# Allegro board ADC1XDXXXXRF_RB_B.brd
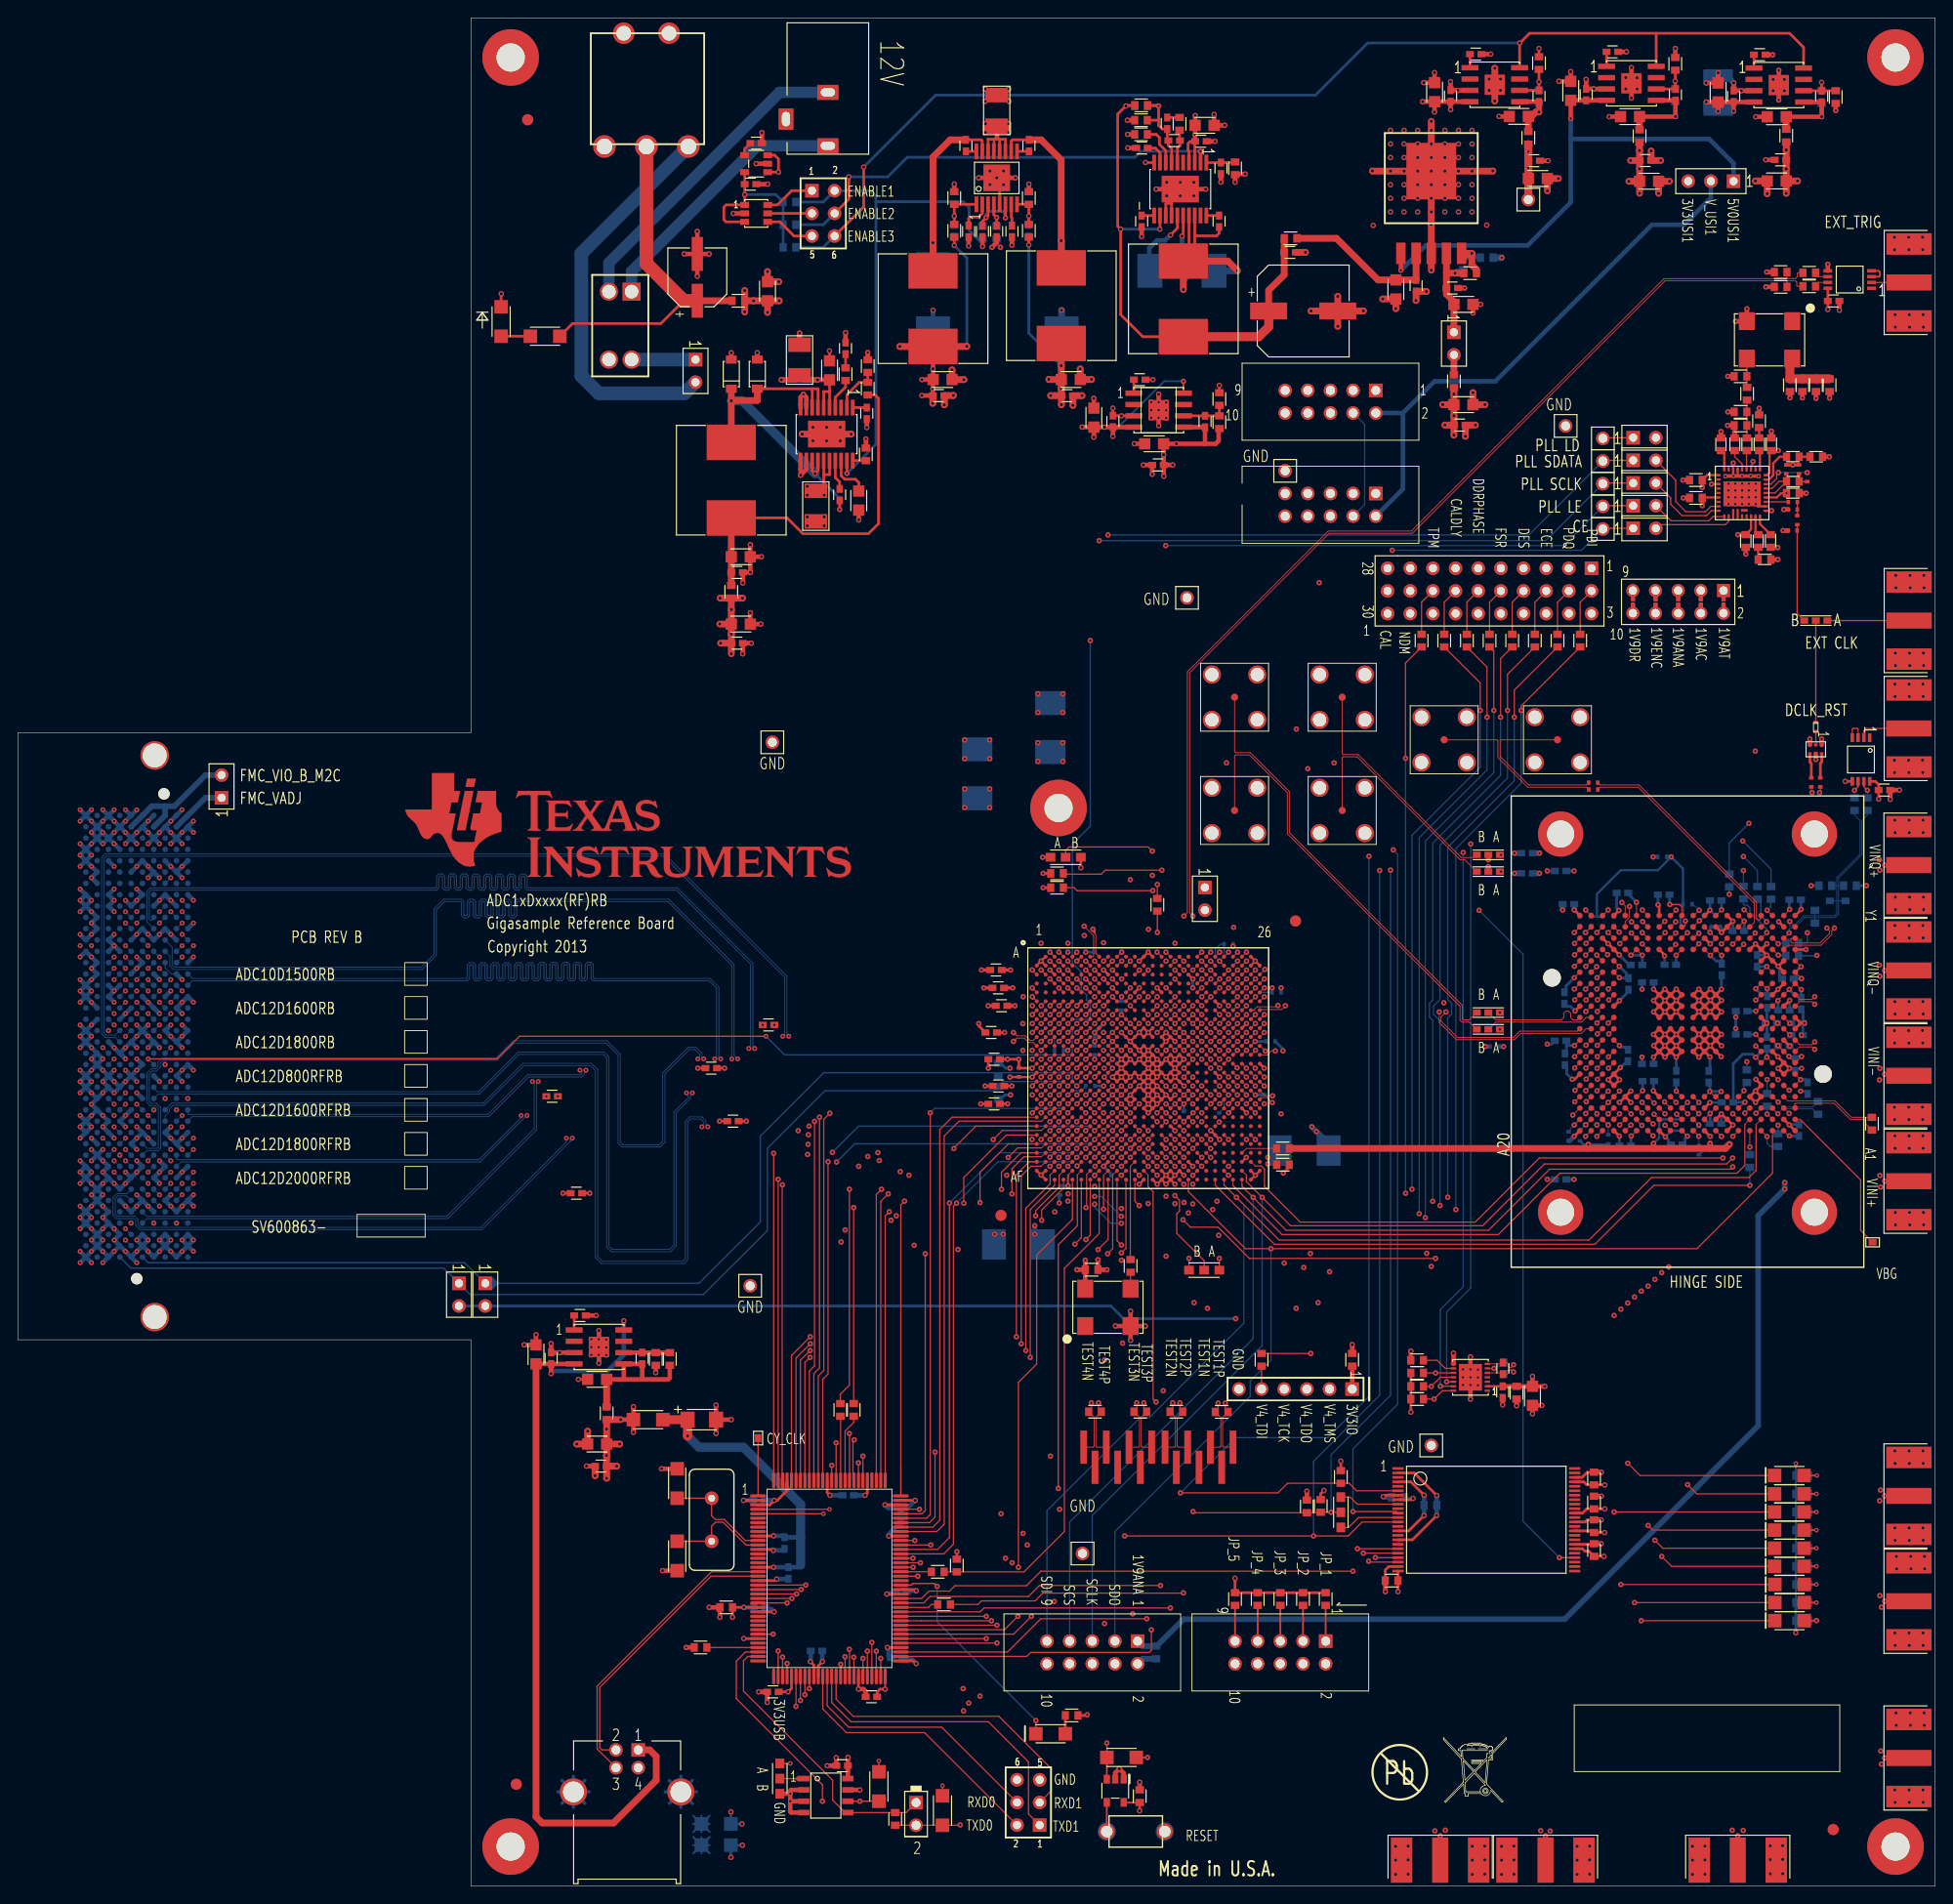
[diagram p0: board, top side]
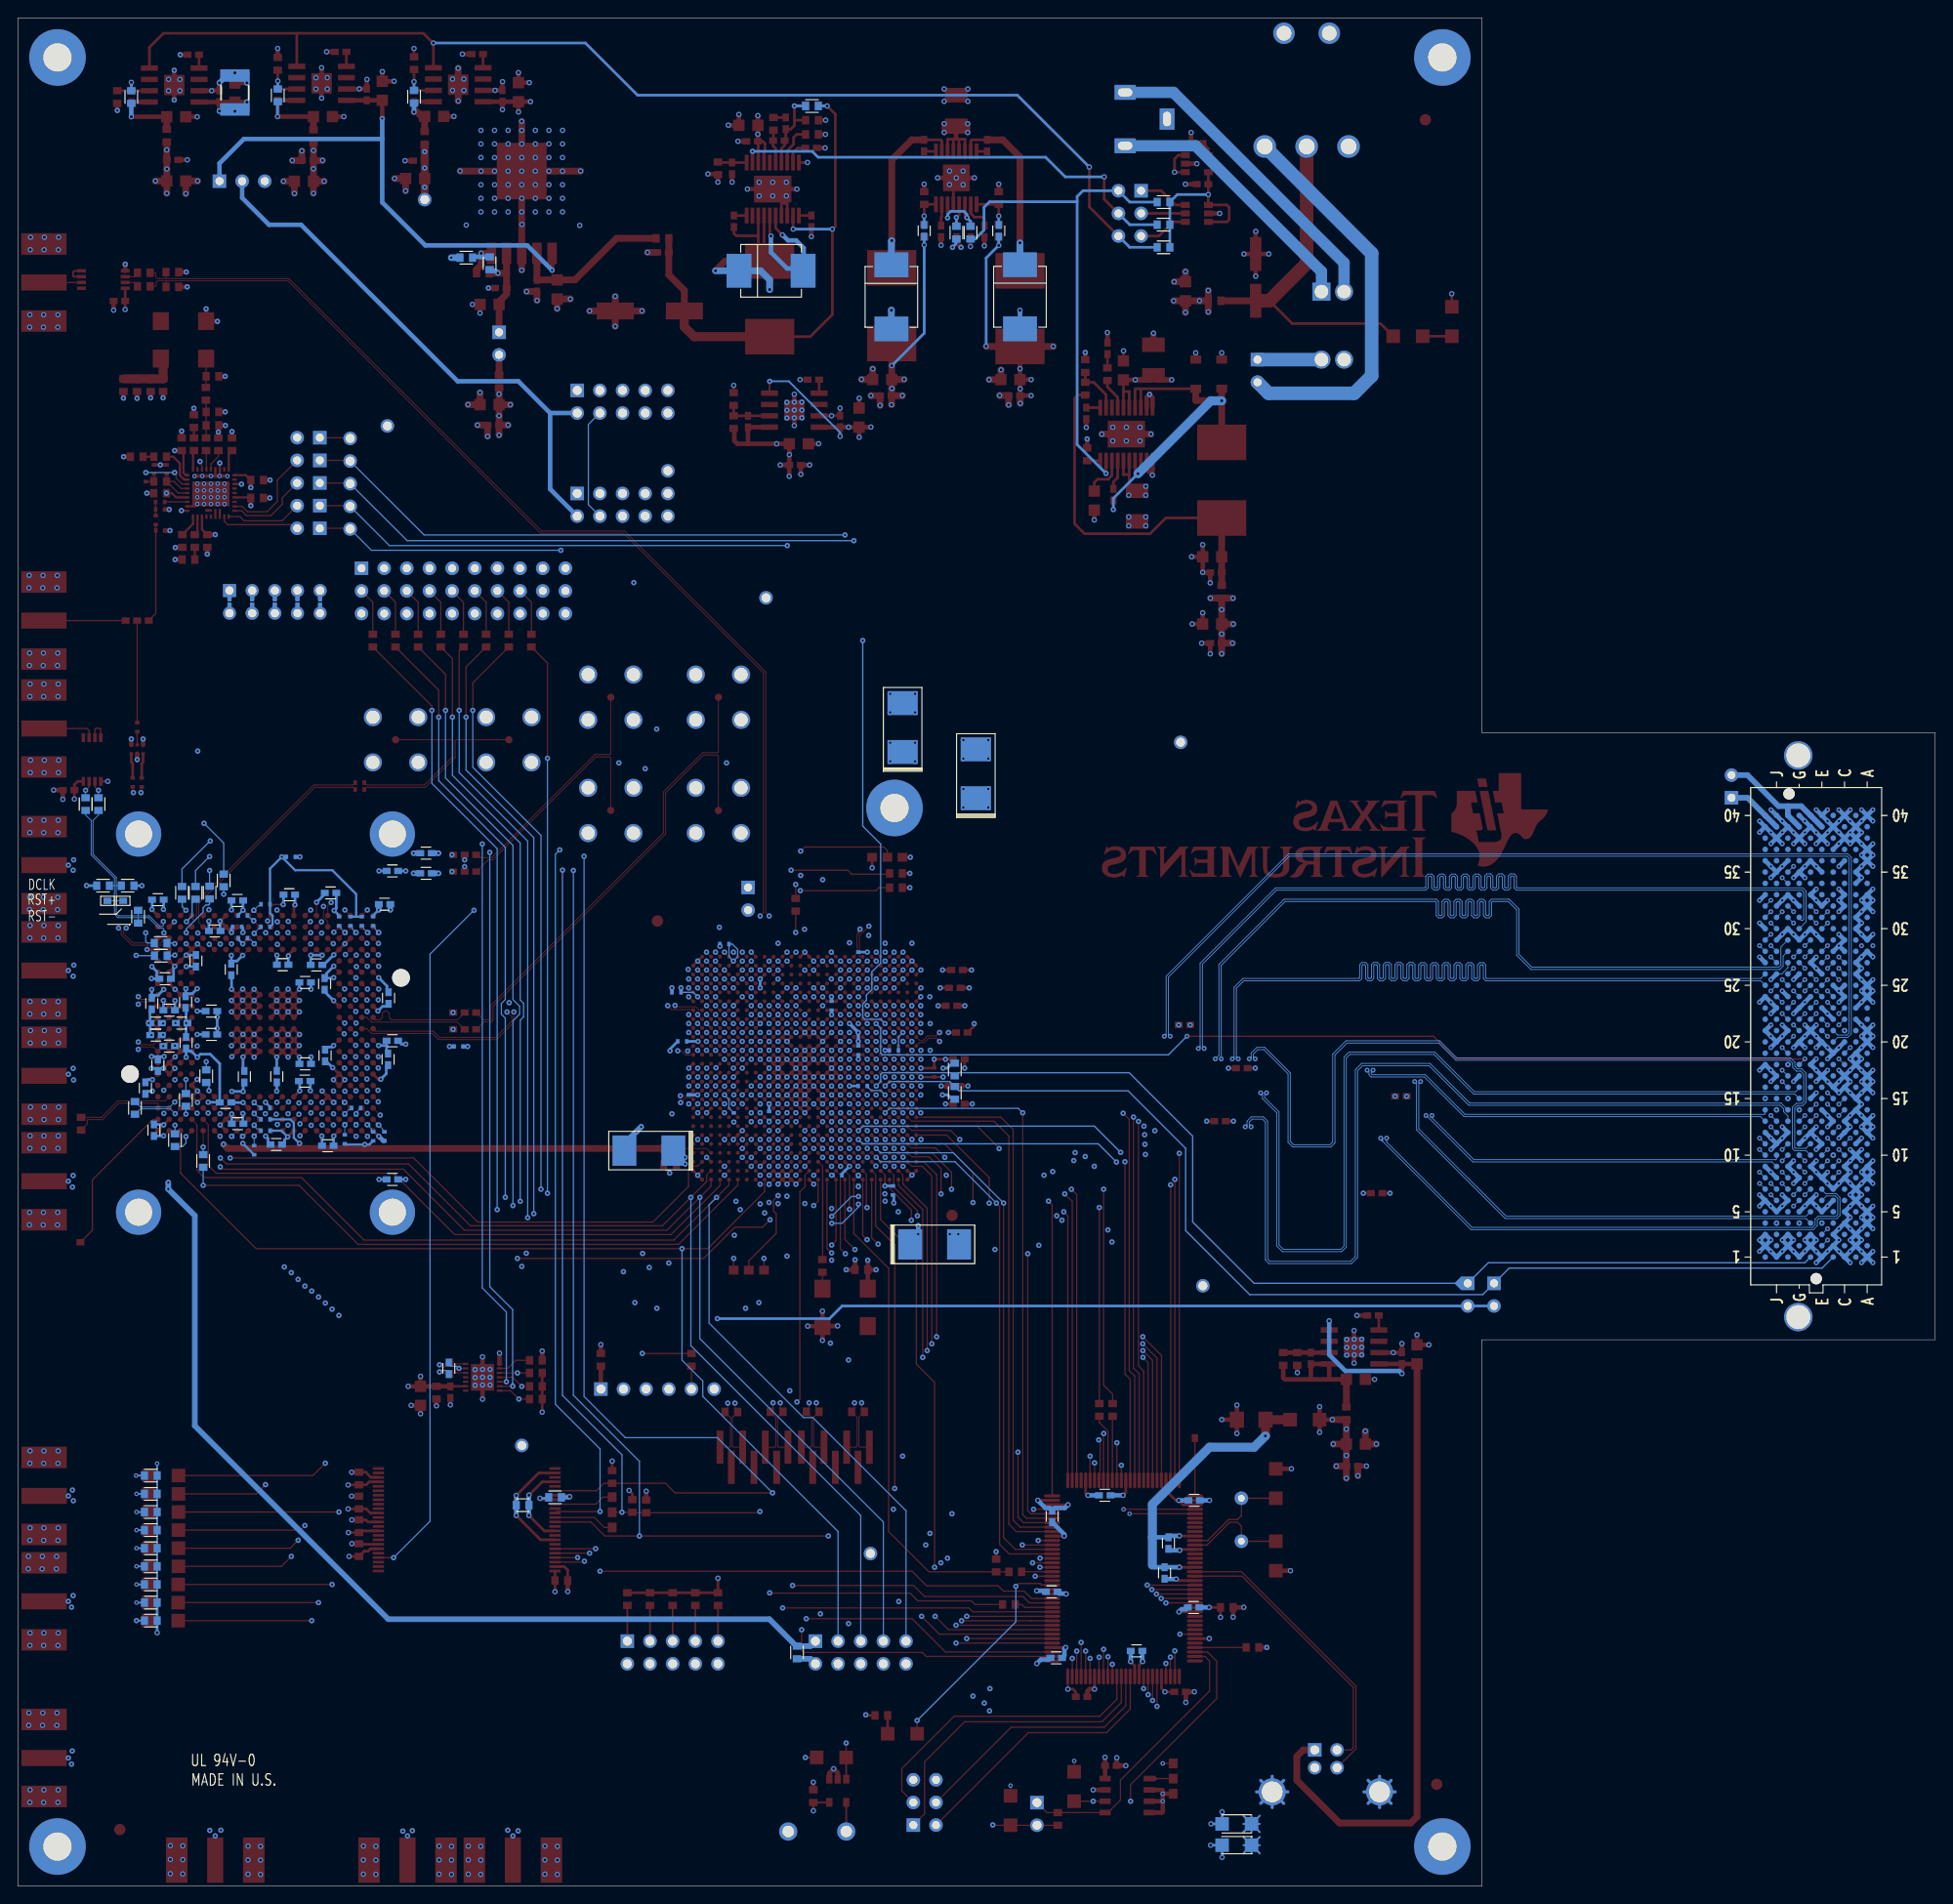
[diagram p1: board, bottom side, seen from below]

Outline 214.93 x 209.55 mm; copper layers: TOP, GND1, SIG1, PWR1, GND2, SIG2, PWR2, SIG3, GND3, BOTTOM. Coordinates in mm from the lower left corner of the outline.
Outline path: 0,129.36 50.8,129.36 50.8,209.55 214.93,209.55 214.93,0 50.8,0 50.8,61.29 0,61.29 0,129.36

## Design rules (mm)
net group CLK: nets CLK+ CLK-
net group DCLK_RST: nets DCLK_RST+ DCLK_RST-
net group DCLKI: nets DCLKI+ DCLKI-
net group DCLKQ: nets DCLKQ+ DCLKQ-
net group DCLKQ_OUT: nets DCLKQ+_OUT DCLKQ-_OUT
net group DCLKQ_PN: nets DCLKQ_N DCLKQ_P
net group DI0: nets DI+0 DI-0
net group DI1: nets DI+1 DI-1
net group DI2: nets DI+2 DI-2
net group DI3: nets DI+3 DI-3
net group DI4: nets DI+4 DI-4
net group DI5: nets DI+5 DI-5
net group DI6: nets DI+6 DI-6
net group DI7: nets DI+7 DI-7
net group DI8: nets DI+8 DI-8
net group DI9: nets DI+9 DI-9
net group DI10: nets DI+10 DI-10
net group DI11: nets DI+11 DI-11
net group DID0: nets DID+0 DID-0
net group DID1: nets DID+1 DID-1
net group DID2: nets DID+2 DID-2
net group DID3: nets DID+3 DID-3
net group DID4: nets DID+4 DID-4
net group DID5: nets DID+5 DID-5
net group DID6: nets DID+6 DID-6
net group DID7: nets DID+7 DID-7
net group DID8: nets DID+8 DID-8
net group DID9: nets DID+9 DID-9
net group DID10: nets DID+10 DID-10
net group DID11: nets DID+11 DID-11
net group DQ0: nets DQ+0 DQ-0
net group DQ1: nets DQ+1 DQ-1
net group DQ2: nets DQ+2 DQ-2
net group DQ3: nets DQ+3 DQ-3
net group DQ4: nets DQ+4 DQ-4
net group DQ5: nets DQ+5 DQ-5
net group DQ6: nets DQ+6 DQ-6
net group DQ7: nets DQ+7 DQ-7
net group DQ8: nets DQ+8 DQ-8
net group DQ9: nets DQ+9 DQ-9
net group DQ10: nets DQ+10 DQ-10
net group DQ11: nets DQ+11 DQ-11
net group DQD0: nets DQD+0 DQD-0
net group DQD1: nets DQD+1 DQD-1
net group DQD2: nets DQD+2 DQD-2
net group DQD3: nets DQD+3 DQD-3
net group DQD4: nets DQD+4 DQD-4
net group DQD5: nets DQD+5 DQD-5
net group DQD6: nets DQD+6 DQD-6
net group DQD7: nets DQD+7 DQD-7
net group DQD8: nets DQD+8 DQD-8
net group DQD9: nets DQD+9 DQD-9
net group DQD10: nets DQD+10 DQD-10
net group DQD11: nets DQD+11 DQD-11
net group EXT_TRIG: nets EXT_TRIG+ EXT_TRIG-
net group FMC_DCLK_DI: nets FMC_DCLK_DI+ FMC_DCLK_DI-
net group FMC_DCLK_DID: nets FMC_DCLK_DID+ FMC_DCLK_DID-
net group FMC_DCLK_DQ: nets FMC_DCLK_DQ+ FMC_DCLK_DQ-
net group FMC_DCLK_DQD: nets FMC_DCLK_DQD+ FMC_DCLK_DQD-
net group FMC_DI0: nets FMC_DI+0 FMC_DI-0
net group FMC_DI1: nets FMC_DI+1 FMC_DI-1
net group FMC_DI2: nets FMC_DI+2 FMC_DI-2
net group FMC_DI3: nets FMC_DI+3 FMC_DI-3
net group FMC_DI4: nets FMC_DI+4 FMC_DI-4
net group FMC_DI5: nets FMC_DI+5 FMC_DI-5
net group FMC_DI6: nets FMC_DI+6 FMC_DI-6
net group FMC_DI7: nets FMC_DI+7 FMC_DI-7
net group FMC_DI8: nets FMC_DI+8 FMC_DI-8
net group FMC_DI9: nets FMC_DI+9 FMC_DI-9
net group FMC_DI10: nets FMC_DI+10 FMC_DI-10
net group FMC_DI11: nets FMC_DI+11 FMC_DI-11
net group FMC_DID0: nets FMC_DID+0 FMC_DID-0
net group FMC_DID1: nets FMC_DID+1 FMC_DID-1
net group FMC_DID2: nets FMC_DID+2 FMC_DID-2
net group FMC_DID3: nets FMC_DID+3 FMC_DID-3
net group FMC_DID4: nets FMC_DID+4 FMC_DID-4
net group FMC_DID5: nets FMC_DID+5 FMC_DID-5
net group FMC_DID6: nets FMC_DID+6 FMC_DID-6
net group FMC_DID7: nets FMC_DID+7 FMC_DID-7
net group FMC_DID8: nets FMC_DID+8 FMC_DID-8
net group FMC_DID9: nets FMC_DID+9 FMC_DID-9
net group FMC_DID10: nets FMC_DID+10 FMC_DID-10
net group FMC_DID11: nets FMC_DID+11 FMC_DID-11
net group FMC_DQ0: nets FMC_DQ+0 FMC_DQ-0
net group FMC_DQ1: nets FMC_DQ+1 FMC_DQ-1
net group FMC_DQ2: nets FMC_DQ+2 FMC_DQ-2
net group FMC_DQ3: nets FMC_DQ+3 FMC_DQ-3
net group FMC_DQ4: nets FMC_DQ+4 FMC_DQ-4
net group FMC_DQ5: nets FMC_DQ+5 FMC_DQ-5
net group FMC_DQ6: nets FMC_DQ+6 FMC_DQ-6
net group FMC_DQ7: nets FMC_DQ+7 FMC_DQ-7
net group FMC_DQ8: nets FMC_DQ+8 FMC_DQ-8
net group FMC_DQ9: nets FMC_DQ+9 FMC_DQ-9
net group FMC_DQ10: nets FMC_DQ+10 FMC_DQ-10
net group FMC_DQ11: nets FMC_DQ+11 FMC_DQ-11
net group FMC_DQD0: nets FMC_DQD+0 FMC_DQD-0
net group FMC_DQD1: nets FMC_DQD+1 FMC_DQD-1
net group FMC_DQD2: nets FMC_DQD+2 FMC_DQD-2
net group FMC_DQD3: nets FMC_DQD+3 FMC_DQD-3
net group FMC_DQD4: nets FMC_DQD+4 FMC_DQD-4
net group FMC_DQD5: nets FMC_DQD+5 FMC_DQD-5
net group FMC_DQD6: nets FMC_DQD+6 FMC_DQD-6
net group FMC_DQD7: nets FMC_DQD+7 FMC_DQD-7
net group FMC_DQD8: nets FMC_DQD+8 FMC_DQD-8
net group FMC_DQD9: nets FMC_DQD+9 FMC_DQD-9
net group FMC_DQD10: nets FMC_DQD+10 FMC_DQD-10
net group FMC_DQD11: nets FMC_DQD+11 FMC_DQD-11
net group FMC_ORI: nets FMC_ORI+ FMC_ORI-
net group FMC_ORQ: nets FMC_ORQ+ FMC_ORQ-
net group FMC_RCOUT1: nets FMC_RCOUT1+ FMC_RCOUT1-
net group FMC_RCOUT2: nets FMC_RCOUT2+ FMC_RCOUT2-
net group ORI: nets ORI+ ORI-
net group ORQ: nets ORQ+ ORQ-
net group RCLK: nets RCLK+ RCLK-
net group RCLK_IN: nets RCLK+_IN RCLK-_IN
net group RCOUT1: nets RCOUT1+ RCOUT1-
net group RCOUT1_OUT: nets RCOUT1+_OUT RCOUT1-_OUT
net group RCOUT1_PN: nets RCOUT1N RCOUT1P
net group RCOUT2: nets RCOUT2+ RCOUT2-
net group REXT: nets N17676520 N17676524
net group RTRIM: nets N17676530 N17676534
net group TEST1: nets TEST1N TEST1P
net group TEST2: nets TEST2N TEST2P
net group TEST3: nets TEST3N TEST3P
net group TEST4: nets TEST4N TEST4P
net group TEST_TRACE: nets N16663537 N16663541
net group VINI: nets VINI+ VINI-
net group VINQ: nets VINQ+ VINQ-
net group TDIODE: nets ADC_TDIODE+ ADC_TDIODE- N16802193

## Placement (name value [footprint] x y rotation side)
ADC_CALIBRATION  GREEN  [R1206]  198.58 37.9 180 top
ADC_POWER  GREEN  [R1206]  198.58 39.93 180 top
C1  100n  [C0402]  199.68 84.79 90 bottom
C1_LF  See Chart  [R0402_NO_SS]  198.25 158.9 90 top
C2  100n  [C0402]  199.24 110.64 0 bottom
C2_LF  See Chart  [C0603]  198.98 157.56 0 top
C3  100n  [C0402]  198.42 101.78 180 bottom
C4  100n  [C0402]  191.01 102.82 270 bottom
C5  100n  [C0402]  189.54 90.79 90 bottom
C6  100n  [C0402]  192.86 107.14 180 bottom
C7  100n  [C0402]  200.63 89.51 270 bottom
C18  100n  [C0402]  184.51 111.2 180 bottom
C19  100n  [C0402]  185.25 103.35 180 bottom
C20  100n  [C0402]  173.38 99.61 270 bottom
C21  100n  [C0402]  179.88 111.4 180 bottom
C22  100n  [C0402]  181.46 103.33 180 bottom
C23  100n  [C0402]  180.55 101.2 270 bottom
C24  100n  [C0402]  180.49 93.17 270 bottom
C25  100n  [C0402_NO_SS]  178.92 87.91 0 bottom
C26  100n  [C0402]  182.78 90.3 0 bottom
C27  100n  [C0402]  180.19 83.05 180 bottom
C28  100n  [C0402]  185.96 83.18 180 bottom
C29  100n  [C0402]  185.91 90.8 90 bottom
C30  100n  [C0402]  173.43 92.74 270 bottom
C34  100n  [C0402]  199.24 92.08 270 bottom
C35  100n  [C0402]  196.08 94.59 90 bottom
C36  100n  [C0402]  199.92 98.99 270 bottom
C37  100n  [C0402]  196.57 96.8 180 bottom
C38  100n  [C0402]  196.13 99.16 270 bottom
C39  100n  [C0402]  197.97 94.22 0 bottom
C40  100n  [C0402]  197.97 98.25 0 bottom
C41  100n  [C0402]  191.65 87.91 180 bottom
C46  100n  [C0402_NO_SS]  190.35 84.1 180 bottom
C47  100n  [C0402]  190.3 85.52 0 bottom
C48  100n  [C0402]  190.33 110.56 180 bottom
C49  100n  [C0402_NO_SS]  190.35 107.59 0 bottom
C52  100n  [C0402]  194.97 103.78 90 bottom
C54  100n  [C0402]  83.07 43.27 0 bottom
C55  100n  [C0402]  83.13 31.27 0 bottom
C56  100n  [C0402]  89.53 26.39 0 bottom
C57  100n  [C0402]  84.65 21.8 180 top
C58  100n  [C0402]  95.69 21.24 180 top
C59  100n  [C0402]  98.53 25.6 0 bottom
C60  100n  [C0402]  99.03 33.02 180 bottom
C61  100n  [C0402]  98.98 41.48 270 bottom
C62  100n  [C0402]  93.09 43.84 180 bottom
C63  0.001uF  [C0603]  79.41 31.27 180 top
C64  2.2uF  [C3216]  76.67 52.32 0 top
C65  10n  [C0402]  86.39 35.13 270 bottom
C66  100n  [C0402]  85.95 38.48 270 bottom
C67  100n  [C0603]  125.76 10.09 90 top
C68  100n  [C0402]  92.41 13.51 180 top
C69  4.7n  [C1206]  78.29 4.6 180 bottom
C70  12pF  [C1206]  73.91 45.16 90 top
C71  12pF  [C1206]  73.91 37.03 270 top
C72  100n  [C0402]  193.23 95.53 180 bottom
C73  100n  [C0402]  199.45 96.8 0 bottom
C74  100n  [C0603]  149.58 59.04 90 top
C75  100p  [C0402]  166.62 58.08 90 bottom
C76  100p  [C0402]  166.48 58.08 90 top
C77  100p  [C0402]  166.45 55.41 270 top
C78  100n  [C0603]  120.37 69.14 0 top
C79  100n  [C0402]  193.23 98.15 180 bottom
C80  10n  [C0402_NO_SS]  126.21 87.74 0 bottom
C81  100n  [C0402_NO_SS]  127.21 95.75 180 bottom
C82  10n  [C0402_NO_SS]  125.21 100.75 0 bottom
C83  100n  [C0402_NO_SS]  128.21 100.75 180 bottom
C84  10n  [C0402_NO_SS]  124.21 82.74 0 bottom
C85  100n  [C0402_NO_SS]  129.2 82.74 180 bottom
C86  10n  [C0402_NO_SS]  125.23 103.76 0 bottom
C87  100n  [C0402_NO_SS]  129.21 103.76 180 bottom
C88  10n  [C0402_NO_SS]  123.06 79.74 180 bottom
C89  10n  [C0402_NO_SS]  131.22 97.75 180 bottom
C90  10n  [C0402_NO_SS]  131.72 102.25 270 bottom
C91  10n  [C0402_NO_SS]  132.22 100.75 180 bottom
C92  10n  [C0402_NO_SS]  132.71 96.25 270 bottom
C93  100n  [C0402_NO_SS]  135.72 105.66 0 bottom
C94  10n  [C0402_NO_SS]  117.71 104.26 90 bottom
C95  10n  [C0402_NO_SS]  118.22 98.75 0 bottom
C96  10n  [C0402_NO_SS]  120.71 104.26 90 bottom
C97  100n  [C0402_NO_SS]  121.21 95.75 0 bottom
C98  100n  [C0402_NO_SS]  128.71 80.24 270 bottom
C99  10n  [C0402_NO_SS]  131.72 96.25 270 bottom
C100  10n  [C0402_NO_SS]  114.22 98.75 180 bottom
C101  10n  [C0402_NO_SS]  120.71 100.25 270 bottom
C102  10n  [C0402_NO_SS]  129.72 85.24 270 bottom
C103  10n  [C0402_NO_SS]  132.22 85.74 0 bottom
C104  10n  [C0402_NO_SS]  132.22 86.74 0 bottom
C105  10n  [C0402_NO_SS]  131.72 83.24 90 bottom
C106  100n  [C0402_NO_SS]  131.72 80.24 90 bottom
C107  100n  [C0402_NO_SS]  135.22 83.74 180 bottom
C108  10n  [C0402_NO_SS]  114.2 83.75 180 bottom
C109  10n  [C0402_NO_SS]  118.21 83.75 0 bottom
C110  10n  [C0402_NO_SS]  116.84 78.03 270 bottom
C111  10n  [C0402_NO_SS]  121.71 88.24 90 bottom
C114  10n  [C0402_NO_SS]  131.72 94.25 90 bottom
C115  10n  [C0402_NO_SS]  132.72 94.25 270 bottom
C116  10n  [C0402_NO_SS]  132.72 89.25 90 bottom
C117  10n  [C0402_NO_SS]  135.72 95.25 90 bottom
C118  10n  [C0402_NO_SS]  134.67 86.22 270 bottom
C119  100n  [C0402_NO_SS]  140.45 94.75 0 bottom
C120  10n  [C0402_NO_SS]  112.21 91.28 270 top
C121  10n  [C0402_NO_SS]  114.2 93.75 180 bottom
C122  10n  [C0402_NO_SS]  114.22 88.75 180 bottom
C123  10n  [C0402_NO_SS]  116.73 93.75 180 bottom
C124  10n  [C0402_NO_SS]  120.22 89.75 0 bottom
C125  100n  [C0402_NO_SS]  120.71 93.75 270 bottom
C126  100n  [C0402_NO_SS]  130.22 78.75 180 bottom
C128  10n  [C0402_NO_SS]  122.21 94.75 180 bottom
C129  10n  [C0402_NO_SS]  122.21 93.75 180 bottom
C130  10n  [C0402_NO_SS]  122.22 89.75 180 bottom
C131  10n  [C0402_NO_SS]  122.71 88.24 270 bottom
C132  10n  [C0402_NO_SS]  123.21 95.75 0 bottom
C134  10n  [C0402_NO_SS]  124.21 88.75 0 bottom
C135  10n  [C0402_NO_SS]  124.21 87.74 0 bottom
C136  100n  [C0603]  168.01 55.35 270 top
C137  100n  [C0603]  200.05 168.35 90 top
C138  100pF  [C0603]  198.65 168.35 90 top
C139  100n  [C0603]  193.83 161.72 270 top
C140  100n  [C0603]  192.46 161.72 270 top
C142  0.47uF  [C0603]  195.2 161.72 90 top
C143  10n  [C0603]  190.93 161.72 90 top
C144  100pF  [C0603]  188.11 157.71 180 top
C145  100pF  [C0603]  196.57 161.72 270 top
C147  0.47uF  [C0603]  198.98 160.32 180 top
C149  100n  [C0603]  188.11 155.7 0 top
C153  100pF  [C0603]  198.98 156.24 0 top
C154  4.7uF  [C0603]  195.1 150.88 270 top
C155  100n  [C0603]  196.49 150.88 90 top
C156  100n  [C0603]  193.7 150.88 90 top
C157  100uF  [C6P6MMX6P6MM]  76.17 180.44 90 top
C158  4.7uF  [C1210]  87.63 171.17 90 top
C159  4.7uF  [C1210]  109.74 199.16 90 top
C160  10u  [C0805]  84.04 178.88 90 top
C161  0.22uF  [C0402]  109.72 185.6 270 top
C162  100n  [C0603]  176.7 40.37 90 top
C163  100n  [C0603]  158.35 42.74 0 bottom
C164  0.1u  [C0402]  106.28 195.22 270 top
C165  0.1u  [C0402]  113.34 195.22 270 top
C166  100n  [C0603]  154.71 43.61 180 bottom
C167  0.1u  [C0402]  103.23 167.19 0 top
C168  10u  [C0805]  103.67 168.98 0 top
C169  10u  [C0805]  118.04 168.98 0 top
C170  0.1u  [C0402]  117.63 167.17 0 top
C171  100n  [C0603]  154.01 34.27 180 top
C172  100n  [C0603]  176.7 37.7 90 top
C173  100n  [C0603]  176.7 45.72 90 top
C174  100n  [C0603]  176.7 43.03 90 top
C175  0.1u  [C0402]  106.58 185.6 270 top
C176  0.1u  [C0402]  111.44 185.6 270 top
C177  1u  [C0402]  108.14 185.6 270 top
C178  27nF  [C0402]  104.97 185.67 270 bottom
C179  27nF  [C0402]  113.33 185.67 270 bottom
C180  10u  [C0805]  120.62 164.71 90 top
C181  0.1u  [C0402]  122.76 164.29 90 top
C182  10u  [C0805]  127.38 161.78 180 top
C183  0.1u  [C0402]  127.81 159.4 180 top
C184  0.1u  [C0402]  80.63 139.42 0 top
C185  0.1u  [C0402]  133.09 164.26 270 top
C186  0.01u  [C0402]  125.76 168.96 0 top
C187  10uF  [1812]  190.61 201.17 90 bottom
C188  0.1u  [C0402]  134.87 192.67 90 top
C189  See Chart  [C0402]  134.66 186.73 270 top
C190  1uF  [C0603]  136.45 192.67 270 top
C191  1u  [C0402]  129.62 195.78 0 top
C192  10u  [C0805]  133.04 197.5 0 top
C193  0.1u  [C0402]  132.62 195.7 0 top
C194  270u  [C10P3MMX10P3MM]  144.09 176.67 0 top
C195  0.1u  [C0402]  142.61 183.24 0 top
C196  0.1u  [C0402]  156.75 179.51 270 top
C197  0.1u  [C0402]  80.62 147.35 0 top
C198  10u  [C0805]  154.48 179.09 270 top
C201  100n  [C0402]  160.8 179.25 0 top
C202  10n  [C0402]  128.85 197.73 90 top
C205  0.01u  [C0402]  125.98 186.73 270 top
C206  100p  [C0402]  126.01 194.96 180 top
C207  10u  [C0805]  190.61 201.17 90 top
C208  0.1u  [C0402]  192.35 200.75 90 top
C209  10u  [C0805]  197.18 198.46 180 top
C210  0.1u  [C0402]  197.59 193.62 180 top
C211  10u  [C0805]  197.18 191.25 180 top
C212  0.1u  [C0402]  202.21 200.73 270 top
C213  10u  [C0805]  58.08 59.65 90 top
C214  0.1u  [C0402]  59.78 59.22 90 top
C215  10u  [C0805]  64.94 56.85 180 top
C216  0.1u  [C0402]  65.36 47.11 180 top
C217  10u  [C0805]  64.94 49.59 180 top
C218  0.01u  [C0402]  195.27 205.41 0 top
C219  0.1u  [C0402]  69.99 59.19 270 top
C220  0.01u  [C0402]  63.01 64.01 0 top
C221  10u  [C0805]  174.08 201.37 90 top
C222  0.1u  [C0402]  175.81 200.95 90 top
C223  10u  [C0805]  180.73 198.47 180 top
C224  0.1u  [C0402]  182.45 193.55 0 top
C225  10u  [C0805]  182.86 191.22 0 top
C226  0.1u  [C0402]  185.82 200.92 270 top
C227  0.01u  [C0402]  178.75 205.73 0 top
C228  10u  [C0805]  158.82 201.21 90 top
C229  0.1u  [C0402]  160.61 200.79 90 top
C230  10u  [C0805]  168.26 198.49 180 top
C231  0.1u  [C0402]  169.98 193.53 0 top
C232  10u  [C0805]  170.4 191.53 0 top
C233  0.1u  [C0402]  170.52 200.77 270 top
C234  0.01u  [C0402]  163.44 205.48 0 top
C235  100n  [C0402]  95.16 165.19 270 top
C236  2.2n  [C0402]  92.79 172.48 90 top
C237  1u  [C0805]  94.26 155.4 270 top
C238  100n  [C0402]  92.13 156.07 270 top
C239  10u  [C0805]  81.04 149.11 0 top
C240  1uF  [C0603]  201.57 168.35 270 top
C241  10u  [C0805]  169.79 54.99 270 top
C242  10u  [C0805]  162.05 166.16 0 top
C243  10u  [C0805]  81.05 141.56 0 top
C244  0.1u  [C0402]  161.64 163.87 0 top
C245  10n  [C0402]  209.25 122.94 0 top
C246  10n  [C0402]  203.55 177.79 0 top
C247  1800pF  [C0603]  162.8 180.91 0 top
C248  10u  [C0805]  162.05 177.41 0 top
C249  100n  [C0402]  109.11 95.75 0 top
C250  100n  [C0402]  109.44 92.75 0 top
C251  100n  [C0402]  109.93 89.75 0 top
C252  100n  [C0402]  109.44 87.74 0 top
C253  100n  [C0402_NO_SS]  130.72 86.39 90 bottom
C254  100n  [C0402]  172.95 113.87 180 bottom
C255  100n  [C0402]  172.95 94.82 180 bottom
C256  100n  [C0402]  172.95 79.27 180 bottom
C257  100n  [C0402]  173.82 110.13 0 bottom
C258  100n  [C0402]  182.73 101.36 0 bottom
C259  100n  [C0402]  182.72 92.23 0 bottom
C260  100n  [C0402_NO_SS]  177.01 86 90 bottom
C261  100n  [C0402]  84.15 96.6 0 top
C262  100n  [C0402]  77.72 91.75 0 top
C263  100n  [C0402]  80.16 85.8 0 top
C264  100n  [C0402]  59.89 88.6 0 top
C265  100n  [C0402]  62.61 77.72 0 top
C266  0.01u  [C0402]  82.77 195.49 0 top
C267  0.1u  [C0402]  82.13 190.89 0 top
C268  100n  [C0402]  199.45 95.45 0 bottom
C269  0.1uF  [C0805]  91 170.01 90 top
C270  4.7uF  [C1210]  89.46 154.79 270 top
C271  100n  [C0402_NO_SS]  122.21 96.75 0 bottom
C272  1u  [C0402_NO_SS]  123.71 98.76 90 bottom
C273  100n  [C0402_NO_SS]  135.21 98.75 180 bottom
C274  1u  [C0402_NO_SS]  141.1 100.25 0 bottom
C275  1u  [C0402_NO_SS]  138.22 83.74 180 bottom
C276  470u  [CAP_C-CASE]  144.2 82.5 0 bottom
C277  10n  [C0402_NO_SS]  122.21 92.75 180 bottom
C278  10n  [C0402_NO_SS]  124.21 86.74 0 bottom
C279  10n  [C0402_NO_SS]  124.21 96.75 180 bottom
C280  10n  [C0402_NO_SS]  123.2 85.74 180 bottom
C281  10n  [C0402_NO_SS]  125.71 96.25 270 bottom
C282  10n  [C0402_NO_SS]  127.21 86.74 180 bottom
C283  100n  [C0402_NO_SS]  129.21 97.75 180 bottom
C284  100n  [C0402_NO_SS]  129.21 86.74 0 bottom
C285  100n  [C0402_NO_SS]  132.22 92.75 0 bottom
C286  10n  [C0402_NO_SS]  123.21 91.75 0 bottom
C287  1u  [C0402_NO_SS]  130.22 91.75 180 bottom
C288  1u  [C0402_NO_SS]  131.21 90.75 0 bottom
C290  470u  [CAP_C-CASE]  115.75 129.95 90 bottom
C291  10n  [C0402_NO_SS]  121.21 85.74 180 bottom
C292  100n  [C0402_NO_SS]  120.71 79.09 270 bottom
C293  1u  [C0402_NO_SS]  122.21 86.74 180 bottom
C294  470u  [CAP_C-CASE]  112.17 71.98 180 bottom
C295  100n  [C0402_NO_SS]  139.72 88.24 270 bottom
C296  1u  [C0402_NO_SS]  139.72 91.25 90 bottom
C297  100n  [C0402_NO_SS]  121.78 91.25 90 bottom
C299  10n  [C0402_NO_SS]  124.71 95.25 270 bottom
C300  10n  [C0402_NO_SS]  123.71 93.25 270 bottom
C301  10n  [C0402_NO_SS]  123.71 90.25 90 bottom
C302  10n  [C0402_NO_SS]  124.71 93.25 270 bottom
C303  10n  [C0402_NO_SS]  124.71 90.25 90 bottom
C304  10n  [C0402_NO_SS]  127.71 93.25 270 bottom
C305  10n  [C0402_NO_SS]  128.71 89.23 270 bottom
C306  10n  [C0402_NO_SS]  128.71 96.24 270 bottom
C307  10n  [C0402_NO_SS]  128.71 94.26 90 bottom
C308  10n  [C0402_NO_SS]  129.72 90.25 90 bottom
C309  100n  [C0402_NO_SS]  128.21 87.74 180 bottom
C310  100n  [C0402_NO_SS]  129.72 95.25 270 bottom
C311  100n  [C0402_NO_SS]  130.72 96.25 90 bottom
C312  100n  [C0402_NO_SS]  129.72 93.25 270 bottom
C313  100n  [C0402_NO_SS]  130.73 89.25 90 bottom
C314  100n  [C0402_NO_SS]  129.72 88.25 90 bottom
C315  100n  [C0402_NO_SS]  131.22 87.74 0 bottom
C316  100n  [C0402_NO_SS]  130.72 93.25 270 bottom
C317  100n  [C0402_NO_SS]  131.72 89.25 90 bottom
C321  100p  [R0402_NO_SS]  198.98 155.24 0 top
C322  470u  [CAP_C-CASE]  107.54 124.76 90 bottom
C323  NA  [C0603]  127.58 26.21 270 bottom
C324  1u  [C0402_NO_SS]  135.72 80.24 90 bottom
C325  100n  [C0402]  110.27 98.75 0 top
C326  100n  [C0402]  109.91 100.75 0 top
C327  100n  [C0402]  109.65 102.76 0 top
C341  4.7n  [C0402_NO_SS]  202.06 123.8 270 top
C342  4.7n  [C0402_NO_SS]  201.05 123.8 270 top
C343  10pF  [C0402_NO_SS]  201.55 130 270 top
C362  100n  [C0402]  169.18 115.86 180 bottom
C363  100n  [C0402]  169.18 113.6 180 bottom
C364  100n  [C0402_NO_SS]  165.53 94.18 0 bottom
C365  100n  [C0402_NO_SS]  184.33 115.44 0 bottom
D1  DIODE SCHOTTKY  [SOD_123_21]  82.9 169.59 90 top
D2  DIODE SCHOTTKY  [DO214_AB]  102.59 178.26 90 bottom
D3  DIODE SCHOTTKY  [DO214_AB]  117.01 178.25 90 bottom
D4  DIODE SCHOTTKY  [DO214_AB]  130.5 181.18 0 bottom
D5  DIODE SCHOTTKY  [SOD_123_21]  79.98 169.59 90 top
DCLK_LOCKED  GREEN  [R1206]  198.58 46.06 180 top
DCLKQ+  SMA_CONN_2  [SMA_V_CLR]  136.4 120.65 0 top
DCLKQ-  SMA_CONN_2  [SMA_V_CLR]  136.4 133.35 0 top
ECM_ENABLED  GREEN  [R1206]  198.61 31.81 180 top
FMC  ASP-134488-01_0  [CONN_SEAM_040]  13.34 95.33 90 bottom
FMC1  TP  [VIA85D55]  15.34 63.83 0 top
FMC2  TP  [VIA85D55]  15.34 126.82 0 top
FPGA_OPERATIONAL  GREEN  [R1206]  198.61 33.84 180 top
J2  USB-B  [USB-JACK-B]  68.3 13.28 0 top
J4  HEADER 10x3  [BLKCON_10X3]  164.98 145.28 270 top
J5  HEADER 2  [BLKCON_2X1]  133.07 110.74 0 top
J6  CONN 6 PIN SINGLE ROW  [SHDR6X1]  149.58 43.05 270 top
J7  sma-3  [RF_SMA_END_LAUNCH]  211.99 79.07 0 top
J8  sma-3  [RF_SMA_END_LAUNCH]  211.99 90.89 0 top
J9  sma-3  [RF_SMA_END_LAUNCH]  211.99 114.52 0 top
J10  sma-3  [RF_SMA_END_LAUNCH]  211.99 102.7 0 top
J12  CONN PWR JACK  [JACK_POWER]  90.81 201.19 180 top
J13  HEADER 3  [BLKCON_3X1]  192.33 191.23 180 top
J14  JUMPER2  [BLKCON_3X2]  89.02 187.62 0 top
J15  CONN 10 PIN  [TH_10_HDR2X5_M_STR_100]  147.15 154.93 270 top
J17  CONN 10 PIN  [TH_10_HDR2X5_M_STR_100]  147.15 166.49 270 top
J18  CONN 10 PIN  [TH_10_HDR2X5_M_STR_100]  141.53 26.21 270 top
J19  sma-3  [RF_SMA_END_LAUNCH]  212.01 129.84 0 top
J20  JUMPER 2X1  [TH_2_HDR1X2_M_STR_100]  100.69 9.37 0 top
J21  JUMPER1  [BLKCON_2X1]  75.97 169.95 0 top
J22  JUMPER1  [BLKCON_2X1]  160.99 173.02 0 top
J23  JUMPER5  [BLKCON_5X2]  186.13 144.05 270 top
J25  HEADER 3X2  [BLKCON_3X2]  114.55 9.39 180 top
J26  sma-3  [RF_SMA_END_LAUNCH]  212.01 179.87 0 top
J27  NA  [RF_SMA_END_LAUNCH]  211.99 14.38 0 top
J28  NA  [RF_SMA_END_LAUNCH]  192.81 2.92 270 top
J29  NA  [RF_SMA_END_LAUNCH]  211.99 43.77 0 top
J30  NA  [RF_SMA_END_LAUNCH]  159.44 2.92 270 top
J31  NA  [RF_SMA_END_LAUNCH]  211.99 31.95 0 top
J32  NA  [RF_SMA_END_LAUNCH]  171.25 2.92 270 top
J34  jumper/sm/small  [SM_JUMPER]  191.21 144.04 270 top
J35  jumper/sm/small  [SM_JUMPER]  191.21 144.04 270 bottom
J36  jumper/sm/small  [SM_JUMPER]  188.67 144.04 270 top
J37  jumper/sm/small  [SM_JUMPER]  188.67 144.04 270 bottom
J38  jumper/sm/small  [SM_JUMPER]  186.13 144.04 270 top
J39  jumper/sm/small  [SM_JUMPER]  186.13 144.04 270 bottom
J40  jumper/sm/small  [SM_JUMPER]  183.59 144.04 270 top
J41  jumper/sm/small  [SM_JUMPER]  183.59 144.04 270 bottom
J42  jumper/sm/small  [SM_JUMPER]  181.05 144.04 270 top
J43  jumper/sm/small  [SM_JUMPER]  181.05 144.04 270 bottom
J44  CONN 10 PIN  [TH_10_HDR2X5_M_STR_100]  120.45 26.21 270 top
J155  HEADER 2  [BLKCON_2X1]  49.45 66.34 0 top
J156  HEADER 2  [BLKCON_2X1]  52.4 66.34 0 top
J157  HEADER 2  [BLKCON_2X1]  22.83 123.34 180 top
J158  JUMPER1  [BLKCON_2X1]  182.35 162.46 90 top
J159  JUMPER1  [BLKCON_2X1]  182.35 159.92 90 top
J160  JUMPER1  [BLKCON_2X1]  182.35 157.38 90 top
J161  JUMPER1  [BLKCON_2X1]  182.35 154.84 90 top
J162  JUMPER1  [BLKCON_2X1]  182.35 152.3 90 top
J163  sma-3  [RF_SMA_END_LAUNCH]  212.01 141.95 0 top
L1  100MHz CHOKE  [R1206]  70.66 52.32 180 top
L2  INDUCTOR FERRITE/SM  [R0603]  142.67 184.82 0 top
L3  INDUCTOR FERRITE/SM  [R0603]  198.24 196.34 270 top
L4  INDUCTOR FERRITE/SM  [R0603]  80.77 177.82 0 top
L5  10uH  [EIA_481]  102.59 176.93 90 top
L6  10uH  [EIA_481]  116.97 177.26 270 top
L7  10uH  [EIA_481]  79.98 157.69 270 top
L8  INDUCTOR FERRITE/SM  [R0603]  79.98 145.18 270 top
L9  CM CHOKE  [CHOKE_CM2545-B]  67.53 175.03 270 top
L10  10uH  [EIA_481]  130.65 178.03 270 top
L11  INDUCTOR FERRITE/SM  [R0603]  66.01 53.04 270 top
L12  INDUCTOR FERRITE/SM  [R0603]  181.8 196.28 270 top
L13  INDUCTOR FERRITE/SM  [R0603]  169.33 196.09 270 top
L14  INDUCTOR FERRITE/SM  [R0603]  160.99 168.78 270 top
LD10  RED  [R1206]  54.18 175.49 90 top
LD11  GREEN  [R1206]  115.77 17.09 180 top
MT1  TP  [VIA85D55]  55.24 4.45 0 top
MT2  TP  [VIA85D55]  210.49 4.45 0 top
MT3  TP  [VIA85D55]  55.24 205.1 0 top
MT4  TP  [VIA85D55]  210.49 205.1 0 top
MT5  TP  [VIA85D55]  116.66 120.93 0 top
NOREF  -  []  0 61.29 90 top
NOREF#2  -  []  163.27 13.18 0 top
NOREF#3  -  [unnamed#2]  55.88 11.43 0 top
NOREF#4  -  []  119.51 247.19 0 top
NOREF#5  -  []  50.8 0 90 top
NOREF#6  -  []  50.8 0 0 top
NOREF#7  -  []  43 112.67 0 top
NOREF#8  -  []  -42.42 254.51 0 top
NOREF#9  -  []  142.06 13.41 0 top
NOREF#10  -  [unnamed#2]  203.5 6.35 0 top
NOREF#11  -  []  152.88 11.51 0 top
NOREF#12  -  [unnamed#2]  143.23 108.25 0 top
NOREF#13  -  [unnamed#2]  110.21 75.23 0 top
NOREF#14  -  []  50.8 0 90 top
NOREF#15  -  []  0 61.29 0 top
NOREF#16  -  []  127.71 1.22 0 top
NOREF#17  -  []  -36.07 242.57 90 top
NOREF#18  -  [unnamed#2]  57.15 198.12 0 top
OVER-RANGE_I-CH  GREEN  [R1206]  198.58 35.87 180 top
OVER-RANGE_Q-CH  GREEN  [R1206]  198.58 44 180 top
R2  49.9  [R0603]  196.53 111.41 270 bottom
R2_LF  See Chart  [R0402_NO_SS]  199.67 158.9 270 top
R3  49.9  [R0603]  195.02 111.41 270 bottom
R4  49.9  [R0603]  196.1 88.19 270 bottom
R5  49.9  [R0603]  193.44 111.44 270 bottom
R6  49.9  [R0603]  191.86 112.8 270 bottom
R7  3.3k  [R0603]  207.84 85.52 90 top
R8  49.9  [R0603]  197.32 83.68 270 bottom
R9  49.9  [R0603]  198.91 104.36 180 bottom
R12  3.3k  [R0603]  201.8 87.29 90 bottom
R13  49.9  [R0603]  92.2 53.42 90 top
R14  49.9  [R0603]  93.7 53.42 90 top
R15  4.7K  [R0603]  105.26 35.97 90 top
R16  49.9  [R0603]  103.12 35.26 0 top
R17  49.9  [R0603]  103.83 31.6 0 top
R18  47K  [R1206]  123.73 14.44 180 top
R19  2.2K  [R1206]  96.52 11.18 90 top
R20  0  [0603_TRIPAD_2_TO_3]  85.42 11.21 270 top
R21  2.2K  [R1206]  103.65 8.48 90 top
R22  0  [R0603]  98.35 7.54 270 top
R23  10k  [R0603]  76.53 26.77 180 top
R24  1M  [R1206]  78.29 6.99 180 bottom
R25  49.9  [R0603]  198.93 105.78 180 bottom
R26  10k  [R0603]  167.52 139.7 90 top
R27  10k  [R0603]  164.98 139.7 90 top
R28  10k  [R0603]  162.44 139.7 90 top
R29  330  [R0603]  116.49 111.99 0 top
R30  100  [R0603]  134.95 53.19 0 top
R31  0  [R0603]  127.74 110.08 270 top
R32  10k  [R0603]  136.45 32.2 270 top
R33  10k  [R0603]  146.61 32.2 270 top
R34  4.7K  [R0603]  116.49 113.59 0 top
R35  10k  [R0603]  138.99 32.2 270 top
R36  10k  [R0603]  141.53 32.2 270 top
R37  10k  [R0603]  144.07 32.2 270 top
R38  0  [0603_TRIPAD_1_TO_2]  133.84 69.09 180 top
R39  100  [R0603]  129.87 53.21 0 top
R40  10K  [0603_TRIPAD_1_TO_2]  116.61 115.4 0 top
R41  100  [R0603]  125.83 53.21 0 top
R42  100  [R0603]  120.75 53.21 0 top
R43  0  [R0603]  139.42 59.04 90 top
R44  10k  [R0603]  175.14 139.7 90 top
R45  10k  [R0603]  172.6 139.7 90 top
R46  10k  [R0603]  170.06 139.7 90 top
R47  330  [R0603]  200.03 39.93 180 bottom
R48  330  [R0603]  200.03 37.9 180 bottom
R49  330  [R0603]  200.03 41.97 180 bottom
R50  330  [R0603]  200.03 35.87 180 bottom
R51  330  [R0603]  200.03 44 180 bottom
R52  330  [R0603]  200.03 33.84 180 bottom
R53  33  [R0603]  124.74 69.57 90 top
R54  330  [R0603]  200.03 46.06 180 bottom
R55  330  [R0603]  200.03 31.81 180 bottom
R58  1k  [R0603]  141.81 82.74 180 top
R59  10k  [R0603]  141.81 80.92 0 top
R65  0  [R0603]  203.1 168.35 90 top
R66  33  [R0603]  193.85 167.39 90 top
R67  150  [R0603]  193.12 169.34 180 top
R68  150  [R0603]  193.12 165.35 180 top
R69  49.9  [R0603]  193.12 163.83 180 top
R70  0  [R0603]  195.2 164.31 90 top
R71  0  [R0603]  201.6 160.32 0 top
R73  DNP  [R0402_NO_SS]  200.58 158.04 270 top
R78  3.3  [R0603]  195.81 148.79 180 top
R81  NA  [R0603]  146.05 42.65 270 top
R82  10  [R0603]  109.72 185.46 270 bottom
R83  NA  [0603_TRIPAD]  148.31 41.94 270 top
R84  NA  [R0603]  144.5 42.6 90 top
R85  3.3k  [R0603]  148.31 45.9 270 top
R86  10k  [R0603]  156.87 54.64 0 top
R87  10k  [R0603]  156.87 56.06 0 top
R88  26.7k  [R0603]  104.97 185.67 90 top
R89  5.9k  [R0603]  104.97 189.34 270 top
R90  5.9k  [R0603]  113.33 189.34 270 top
R91  18.7k  [R0603]  113.33 185.67 90 top
R92  205k  [R0603]  95.06 160.59 270 top
R93  1k  [R0603]  92.79 169.58 270 top
R94  15k  [R0603]  95.28 167.96 90 top
R95  30k  [R0603]  95.28 170.49 270 top
R96  5.1k  [R0603]  108.14 185.46 270 bottom
R97  2.2k  [R0603]  134.69 166.8 270 top
R98  1.8k  [R0603]  134.69 164.2 90 top
R99  1.2K  [R1206]  59.11 173.84 0 top
R103  47.5k  [R0603]  130.23 197.66 90 top
R104  10k  [R0603]  156.87 57.56 0 top
R105  NA  [R0603]  125.91 199.66 0 bottom
R106  See Chart  [R0603]  125.93 199.74 0 top
R107  See Chart  [R0603]  125.91 198.06 0 top
R108  20k  [R0603]  125.91 196.48 0 top
R109  1.3k  [R0603]  203.79 200.67 90 top
R110  5.1k  [R0603]  202.21 200.67 90 bottom
R111  1k  [R0603]  71.51 59.13 90 top
R112  2.4k  [R0603]  73.09 59.13 90 top
R113  10k  [R0603]  159.9 139.7 90 top
R114  10k  [R0603]  157.36 139.7 90 top
R115  330  [R0603]  200.03 29.78 180 bottom
R117  1k  [R0603]  185.8 204.39 270 top
R118  2.4k  [R0603]  185.79 200.86 90 bottom
R120  22k  [R0603]  86.5 188.89 180 bottom
R121  22k  [R0603]  86.5 186.35 180 bottom
R122  22k  [R0603]  86.5 183.81 180 bottom
R124  1k  [R0603]  170.52 204.47 270 top
R125  2k  [R0603]  170.52 200.7 90 bottom
R126  0  [R0603]  156.86 58.98 180 top
R127  49.9  [R0603]  194.16 81.34 90 bottom
R128  49.9  [R0603]  193.82 90.85 270 bottom
R129  33  [R0603]  205.89 121.36 270 bottom
R130  95.3  [R0603]  202.63 112.21 180 bottom
R131  33  [R0603]  207.34 121.36 270 bottom
R132  95.3  [R0603]  205.38 112.21 0 bottom
R133  NA  [R0603]  201.45 108.74 270 bottom
R134  33  [R0603]  200.81 180.95 180 top
R135  95.3  [R0603]  197.61 181.03 180 top
R136  33  [R0603]  200.81 179.44 180 top
R137  95.3  [R0603]  197.61 179.37 180 top
R142  330  [R0603]  118.14 19.15 0 top
R145  NA  [R0402_NO_SS]  176.61 123.76 180 top
R147  NA  [R0402_NO_SS]  176.61 123 180 top
R149  See Chart  [R0603]  162.05 182.03 90 bottom
R150  806  [R0603]  164.67 182.65 0 bottom
R155  10k  [R0603]  109.91 88.98 90 bottom
R156  10k  [R0603]  109.91 91.59 90 bottom
R159  0  [0402_TRIPAD_1_TO_2]  165.49 113.79 180 top
R160  0  [0402_TRIPAD_1_TO_2]  165.49 115.67 180 top
R161  0  [0402_TRIPAD_1_TO_2]  165.49 97.98 180 top
R162  0  [0402_TRIPAD_1_TO_2]  165.49 96.1 180 top
R180  0  [0402_TRIPAD_2_TO_3]  200.91 141.95 180 top
R195  0  [R0402_NO_SS]  199.47 153.21 90 top
R196  DNP  [R0402_NO_SS]  198.98 154.41 180 top
R197  DNP  [R0402_NO_SS]  198.96 152.04 180 top
R203  See Chart  [R0402_NO_SS]  188.44 84.73 270 bottom
R204  See Chart  [R0402_NO_SS]  188.44 82.55 270 bottom
R205  See Chart  [R0402_NO_SS]  187.17 84.73 0 bottom
R206  See Chart  [R0402_NO_SS]  188.44 87.27 270 bottom
R207  See Chart  [R0402_NO_SS]  187.17 86 180 bottom
R208  See Chart  [R0402_NO_SS]  187.17 87.27 0 bottom
R209  See Chart  [R0402_NO_SS]  178.28 86 270 bottom
R210  See Chart  [R0402_NO_SS]  178.28 83.77 270 bottom
R211  See Chart  [R0402_NO_SS]  177.01 87.27 0 bottom
R212  See Chart  [R0402_NO_SS]  175.12 85.4 0 bottom
R213  See Chart  [R0402_NO_SS]  175.11 84.1 270 bottom
R214  See Chart  [R0402_NO_SS]  173.84 84.1 90 bottom
R215  See Chart  [R0402_NO_SS]  177.65 106.96 180 bottom
R216  See Chart  [R0402_NO_SS]  177.65 108.23 90 bottom
R217  See Chart  [R0402_NO_SS]  178.92 108.23 270 bottom
R218  See Chart  [R0402_NO_SS]  175.11 106.96 0 bottom
R219  See Chart  [R0402_NO_SS]  176.38 108.23 90 bottom
R220  See Chart  [R0402_NO_SS]  175.11 108.23 270 bottom
R221  See Chart  [R0402_NO_SS]  188.49 108.86 90 bottom
R222  See Chart  [R0402_NO_SS]  187.17 110.13 180 bottom
R223  See Chart  [R0402_NO_SS]  189.71 108.86 180 bottom
R224  See Chart  [R0402_NO_SS]  188.44 106.29 90 bottom
R225  See Chart  [R0402_NO_SS]  187.17 107.59 180 bottom
R226  See Chart  [R0402_NO_SS]  189.71 106.32 180 bottom
RCLK+  SMA_CONN_2  [SMA_V_CLR]  172.59 128.58 0 top
RCLK-  SMA_CONN_2  [SMA_V_CLR]  159.89 128.58 0 top
RCOUT1+  SMA_CONN_2  [SMA_V_CLR]  148.46 133.35 0 top
RCOUT1-  SMA_CONN_2  [SMA_V_CLR]  148.46 120.65 0 top
RCOUT1/2_ENABLED  GREEN  [R1206]  198.61 29.78 180 top
SW1  RESET  [SW_2P_6X3P5]  122.07 6.13 0 top
SW2  ROCKER  [SW_TH_RA_7101]  70.46 201.98 0 top
T2  B0430J50100AHF  [SOIC6_026_WG049_L079]  201.56 127.51 270 top
TP1  TP_VBG  [TP_SMD_S35X28]  207.92 72.22 180 top
TP2  TP_CY_CLK  [TP_SMD_S35X28]  82.99 50.26 90 top
TP3  TP_DCLK_RST_N  [TP_SMD_S35X28]  203.13 110.52 180 bottom
TP4  TP_DCLK_RST_P  [TP_SMD_S35X28]  204.89 110.51 180 bottom
TP5  TP  [TP40]  142.07 158.74 0 top
TP6  TP  [TP40]  84.58 128.3 0 top
TP7  TP  [TP40]  82.09 67.34 0 top
TP8  TP  [TP40]  158.45 49.43 0 top
TP9  TP  [TP40]  131.06 144.5 0 top
TP10  TP  [TP40]  173.51 163.78 0 top
TP11  TP  [TP40]  119.35 37.31 0 top
TP15  TP  [TP40]  169.33 189.17 0 top
TP16  TP  [TP40]  177.68 162.38 0 top
TP17  TP  [TP40]  177.68 159.84 0 top
TP18  TP  [TP40]  177.68 157.3 0 top
TP19  TP  [TP40]  177.68 154.76 0 top
TP20  TP  [TP40]  177.68 152.22 0 top
TRIGGER_ARMED  GREEN  [R1206]  198.58 41.97 180 top
U1  ADC1xDxxxxRFIUT/NOPB  [SOCKET_BGA_05_292_B025]  187.17 96.8 90 top
U2  Cypress CY7C68013A-128AXC  [128TQFP]  90.98 34.52 0 top
U3  LM3724  [SOT23-STX]  123.02 10.7 180 top
U4  24C02  [SOIC8]  90.58 10.16 0 top
U5  XC4VLX25-11FFG668  [BGA_668_27X27_1P0]  126.72 91.74 0 top
U6  NA  [SM_7PIN_FTR]  132.41 48.11 270 top
U7  NA  [SM_7PIN_FTR]  123.29 48.11 270 top
U8  LM95233  [LLP14_P5MM_4X4_EP]  162.84 57.07 180 top
U12  LMX2531LQ1xxxE  [LLP39_P5MM_6X6]  193.29 156.26 90 top
U13  LM26400  [TSSOP16_65M_WG6P4_L5]  109.74 191.6 90 top
U14  XCF08P_VO48 N/A  [TSSOP48_50M_WG20_L12]  164.62 41.1 0 top
U15  LP3878SD  [SOIC8_050_WG244_L200_EP]  127.89 165.55 0 top
U16  LM25576  [TSSOP20_65M_WG6P4_L6P5_EP]  130.31 190.35 270 top
U17  LP38513-ADJ  [SC-MKT-TJ5A]  158.45 188.72 0 top
U18  LP3878SD  [SOIC8_050_WG244_L200_EP]  197.4 202.01 0 top
U19  LP3878SD  [SOIC8_050_WG244_L200_EP]  65.15 60.48 0 top
U20  LP3878SD  [SOIC8_050_WG244_L200_EP]  180.88 202.2 0 top
U21  LM3880  [SOT_23_6]  82.77 187.62 0 top
U22  LP3878SD  [SOIC8_050_WG244_L200_EP]  165.57 202.05 0 top
U23  LM20242  [TSSOP20_65M_WG6P4_L6P5_EP]  90.67 162.86 270 top
U24  MC100EP16  [TSSOP8_65M_WG4P9_L3]  206.62 126.36 270 top
U25  MC100EP16  [TSSOP8_65M_WG4P9_L3]  205.35 180.2 180 top
U29  LP2992IM5-5.0  [SC-MKT-MF05A]  82.77 193.19 180 top
Y1  XTAL 24MHz  [HC49US]  77.77 41.1 90 top
Y2  OSC 100MHz  [OSC_100M_5X7]  122.2 64.92 180 top
Y3  CLK_OSC  [OSC_100M_5X7]  196.37 173.43 0 top

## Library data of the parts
ADC_CALIBRATION ADC_POWER DCLK_LOCKED ECM_ENABLED FPGA_OPERATIONAL LD10 LD11 OVER-RANGE_I-CH OVER-RANGE_Q-CH RCOUT1/2_ENABLED TRIGGER_ARMED = LED_SNGLE_PANEL
C1 C1_LF C2 C2_LF C3-C7 C18-C30 C34-C41 C46-C49 C52 C67 C72-C111 C114-C126 C128-C132 C134-C140 C142-C145 C147 C149 C153-C156 C162 C163 C166 C171-C174 C240 C245-C247 C249-C265 C268 C271-C275 C277-C288 C291-C293 C295-C297 C299-C317 C321 C324-C327 C341-C343 C362-C365 = C-NON-POL
C54-C63 C65 C66 C68-C71 C158-C161 C164 C165 C167 C170 C175-C181 C183-C193 C195-C198 C201 C202 C205-C208 C210 C212-C214 C216 C218-C222 C224 C226-C229 C231 C233-C238 C244 C248 C266 C267 C269 C270 C323 = CAPACITOR NON-POL
C64 C157 C168 C169 C182 C194 C209 C211 C215 C217 C223 C225 C230 C232 C239 C241-C243 C276 C290 C294 C322 = C-POLARISED
D1-D5 = DIODE SCHOTTKY
DCLKQ+ DCLKQ- RCLK+ RCLK- RCOUT1+ RCOUT1- = SMA_CONN_2
FMC = ASP-134488-01_0
FMC1 FMC2 MT1-MT5 TP1-TP11 TP15-TP20 = TEST POINT
J2 = USB-B_0
J4 = HEADER 10x3
J5 J155-J157 = HEADER 2
J6 = CONN 6 PIN SINGLE ROW
J7-J10 J19 J26-J32 J163 = sma-3_0
J12 = CONN PWR JACK
J13 = HEADER 3
J14 = JUMPER3
J15 J17 J18 J44 = CONN 10 PIN 2mm SMT DUAL ROW
J20 = JUMPER 2X1
J21 J22 J158-J162 = JUMPER1
J23 = JUMPER5
J25 = HEADER 3X2
J34-J43 = jumper/sm/small
L1 = CHOKE
L2-L4 L8 L11-L14 = INDUCTOR FERRITE/SM
L5-L7 L10 = INDUCTOR
L9 = INDUCTOR CM CHOKE
R2 R2_LF R3-R9 R12-R19 R21-R37 R39 R41-R55 R58 R59 R65-R71 R73 R78 R81 R82 R84-R99 R103-R115 R117 R118 R120-R122 R124-R137 R142 R145 R147 R149 R150 R155 R156 R195-R197 R203-R226 = RESISTOR
R20 R38 R40 R83 R159-R162 R180 = RESISTOR_TRIPAD
SW1 = SW KEY-SPST
SW2 = SW-DPST-2P
T2 = TRANSFORMER AIR CORE_0
U1 = ADC12D800RF
U2 = Cypress CY7C64613-80NC
U3 = LM3722
U4 = 24C02/SO8_0: Tolerance: ***; User Part Number: ***
U5 = XC4VLX25-11FFG668 _3
U6 U7 = 2MM_7PIN_HEADER
U8 = LM95233
U12 = LMX2531LQ1500E
U13 = LM26400
U14 = XCF08P_VO48_1
U15 U18-U20 U22 = LP3878SD
U16 = LM25576
U17 = LP38513-ADJ
U21 = LM3880
U23 = LM20242
U24 U25 = MC10EP16
U29 = LP2992IM5-5.0
Y1 = CRYSTAL
Y2 = OSC-SM
Y3 = Oscillator/4smd_0

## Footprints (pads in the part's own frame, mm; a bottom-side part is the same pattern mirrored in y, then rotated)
128TQFP
  oval 1.803x0.356 smd: 1(-8.001,9.253) 2(-8.001,8.753) 3(-8.001,8.252) 4(-8.001,7.752) 5(-8.001,7.252) 6(-8.001,6.751) 7(-8.001,6.251) 8(-8.001,5.751) 9(-8.001,5.253) 10(-8.001,4.752) 11(-8.001,4.252) 12(-8.001,3.752) 13(-8.001,3.251) 14(-8.001,2.751) 15(-8.001,2.25) 16(-8.001,1.75) 17(-8.001,1.25) 18(-8.001,0.749) 19(-8.001,0.251) 20(-8.001,-0.249) 21(-8.001,-0.749) 22(-8.001,-1.25) 23(-8.001,-1.75) 24(-8.001,-2.25) 25(-8.001,-2.751) 26(-8.001,-3.251) 27(-8.001,-3.752) 28(-8.001,-4.252) 29(-8.001,-4.752) 30(-8.001,-5.25) 31(-8.001,-5.751) 32(-8.001,-6.251) 33(-8.001,-6.751) 34(-8.001,-7.252) 35(-8.001,-7.752) 36(-8.001,-8.252) 37(-8.001,-8.753) 38(-8.001,-9.253) 65(8.001,-9.253) 66(8.001,-8.753) 67(8.001,-8.252) 68(8.001,-7.752) 69(8.001,-7.252) 70(8.001,-6.751) 71(8.001,-6.251) 72(8.001,-5.751) 73(8.001,-5.253) 74(8.001,-4.752) 75(8.001,-4.252) 76(8.001,-3.752) 77(8.001,-3.251) 78(8.001,-2.751) 79(8.001,-2.25) 80(8.001,-1.75) 81(8.001,-1.25) 82(8.001,-0.749) 83(8.001,-0.251) 84(8.001,0.249) 85(8.001,0.749) 86(8.001,1.25) 87(8.001,1.75) 88(8.001,2.25) 89(8.001,2.751) 90(8.001,3.251) 91(8.001,3.752) 92(8.001,4.252) 93(8.001,4.752) 94(8.001,5.25) 95(8.001,5.751) 96(8.001,6.251) 97(8.001,6.751) 98(8.001,7.252) 99(8.001,7.752) 100(8.001,8.252) 101(8.001,8.753) 102(8.001,9.253)
  oval 0.356x1.803 smd: 39(-6.251,-11.001) 40(-5.751,-11.001) 41(-5.253,-11.001) 42(-4.752,-11.001) 43(-4.252,-11.001) 44(-3.752,-11.001) 45(-3.251,-11.001) 46(-2.751,-11.001) 47(-2.25,-11.001) 48(-1.75,-11.001) 49(-1.25,-11.001) 50(-0.749,-11.001) 51(-0.251,-11.001) 52(0.249,-11.001) 53(0.749,-11.001) 54(1.25,-11.001) 55(1.75,-11.001) 56(2.25,-11.001) 57(2.751,-11.001) 58(3.251,-11.001) 59(3.752,-11.001) 60(4.252,-11.001) 61(4.752,-11.001) 62(5.25,-11.001) 63(5.751,-11.001) 64(6.251,-11.001) 103(6.251,11.001) 104(5.751,11.001) 105(5.253,11.001) 106(4.752,11.001) 107(4.252,11.001) 108(3.752,11.001) 109(3.251,11.001) 110(2.751,11.001) 111(2.25,11.001) 112(1.75,11.001) 113(1.25,11.001) 114(0.749,11.001) 115(0.251,11.001) 116(-0.249,11.001) 117(-0.749,11.001) 118(-1.25,11.001) 119(-1.75,11.001) 120(-2.25,11.001) 121(-2.751,11.001) 122(-3.251,11.001) 123(-3.752,11.001) 124(-4.252,11.001) 125(-4.752,11.001) 126(-5.25,11.001) 127(-5.751,11.001) 128(-6.251,11.001)
0402_TRIPAD_1_TO_2
  rect 0.889x0.711 smd: 1(-0.648,0) 2(0.648,0) 3(1.943,0)
0402_TRIPAD_2_TO_3
  rect 0.889x0.711 smd: 1(-1.943,0) 2(-0.648,0) 3(0.648,0)
0603_TRIPAD
  rect 1.092x0.991 smd: 1(-1.702,0) 2(0,0) 3(1.702,0)
0603_TRIPAD_1_TO_2
  rect 1.092x0.991 smd: 1(-0.851,0) 2(0.851,0) 3(2.553,0)
0603_TRIPAD_2_TO_3
  rect 1.092x0.991 smd: 1(-2.553,0) 2(-0.851,0) 3(0.851,0)
1812
  rect 1.4x3.3 smd: 1(-1.905,0) 2(1.905,0)
BGA_668_27X27_1P0
  round 0.457 smd: A2(-11.501,12.499) A3(-10.5,12.499) A4(-9.5,12.499) A5(-8.499,12.499) A6(-7.501,12.499) A7(-6.5,12.499) A8(-5.499,12.499) A9(-4.501,12.499) A10(-3.5,12.499) A11(-2.499,12.499) A12(-1.501,12.499) A13(-0.5,12.499) A14(0.5,12.499) A15(1.501,12.499) A16(2.499,12.499) A17(3.5,12.499) A18(4.501,12.499) A19(5.499,12.499) A20(6.5,12.499) A21(7.501,12.499) A22(8.499,12.499) A23(9.5,12.499) A24(10.5,12.499) A25(11.501,12.499) AA1(-12.499,-7.501) AA2(-11.501,-7.501) AA3(-10.5,-7.501) AA4(-9.5,-7.501) AA5(-8.499,-7.501) AA6(-7.501,-7.501) AA7(-6.5,-7.501) AA8(-5.499,-7.501) AA9(-4.501,-7.501) AA10(-3.5,-7.501) AA11(-2.499,-7.501) AA12(-1.501,-7.501) AA13(-0.5,-7.501) AA14(0.5,-7.501) AA15(1.501,-7.501) AA16(2.499,-7.501) AA17(3.5,-7.501) AA18(4.501,-7.501) AA19(5.499,-7.501) AA20(6.5,-7.501) AA21(7.501,-7.501) AA22(8.499,-7.501) AA23(9.5,-7.501) AA24(10.5,-7.501) AA25(11.501,-7.501) AA26(12.499,-7.501) AB1(-12.499,-8.499) AB2(-11.501,-8.499) AB3(-10.5,-8.499) AB4(-9.5,-8.499) AB5(-8.499,-8.499) AB6(-7.501,-8.499) AB7(-6.5,-8.499) AB8(-5.499,-8.499) AB9(-4.501,-8.499) AB10(-3.5,-8.499) AB11(-2.499,-8.499) AB12(-1.501,-8.499) AB13(-0.5,-8.499) AB14(0.5,-8.499) AB15(1.501,-8.499) AB16(2.499,-8.499) AB17(3.5,-8.499) AB18(4.501,-8.499) AB19(5.499,-8.499) AB20(6.5,-8.499) AB21(7.501,-8.499) AB22(8.499,-8.499) AB23(9.5,-8.499) AB24(10.5,-8.499) AB25(11.501,-8.499) AB26(12.499,-8.499) AC1(-12.499,-9.5) AC2(-11.501,-9.5) AC3(-10.5,-9.5) AC4(-9.5,-9.5) AC5(-8.499,-9.5) AC6(-7.501,-9.5) AC7(-6.5,-9.5) AC8(-5.499,-9.5) AC9(-4.501,-9.5) AC10(-3.5,-9.5) AC11(-2.499,-9.5) AC12(-1.501,-9.5) AC13(-0.5,-9.5) AC14(0.5,-9.5) AC15(1.501,-9.5) AC16(2.499,-9.5) AC17(3.5,-9.5) AC18(4.501,-9.5) AC19(5.499,-9.5) AC20(6.5,-9.5) AC21(7.501,-9.5) AC22(8.499,-9.5) AC23(9.5,-9.5) AC24(10.5,-9.5) AC25(11.501,-9.5) AC26(12.499,-9.5) AD1(-12.499,-10.5) AD2(-11.501,-10.5) AD3(-10.5,-10.5) AD4(-9.5,-10.5) AD5(-8.499,-10.5) AD6(-7.501,-10.5) AD7(-6.5,-10.5) AD8(-5.499,-10.5) AD9(-4.501,-10.5) AD10(-3.5,-10.5) AD11(-2.499,-10.5) AD12(-1.501,-10.5) AD13(-0.5,-10.5) AD14(0.5,-10.5) AD15(1.501,-10.5) AD16(2.499,-10.5) AD17(3.5,-10.5) AD18(4.501,-10.5) AD19(5.499,-10.5) AD20(6.5,-10.5) AD21(7.501,-10.5) AD22(8.499,-10.5) AD23(9.5,-10.5) AD24(10.5,-10.5) AD25(11.501,-10.5) AD26(12.499,-10.5) AE1(-12.499,-11.501) AE2(-11.501,-11.501) AE3(-10.5,-11.501) AE4(-9.5,-11.501) AE5(-8.499,-11.501) AE6(-7.501,-11.501) AE7(-6.5,-11.501) AE8(-5.499,-11.501) AE9(-4.501,-11.501) AE10(-3.5,-11.501) AE11(-2.499,-11.501) AE12(-1.501,-11.501) AE13(-0.5,-11.501) AE14(0.5,-11.501) AE15(1.501,-11.501) AE16(2.499,-11.501) AE17(3.5,-11.501) AE18(4.501,-11.501) AE19(5.499,-11.501) AE20(6.5,-11.501) AE21(7.501,-11.501) AE22(8.499,-11.501) AE23(9.5,-11.501) AE24(10.5,-11.501) AE25(11.501,-11.501) AE26(12.499,-11.501) AF2(-11.501,-12.499) AF3(-10.5,-12.499) AF4(-9.5,-12.499) AF5(-8.499,-12.499) AF6(-7.501,-12.499) AF7(-6.5,-12.499) AF8(-5.499,-12.499) AF9(-4.501,-12.499) AF10(-3.5,-12.499) AF11(-2.499,-12.499) AF12(-1.501,-12.499) AF13(-0.5,-12.499) AF14(0.5,-12.499) AF15(1.501,-12.499) AF16(2.499,-12.499) AF17(3.5,-12.499) AF18(4.501,-12.499) AF19(5.499,-12.499) AF20(6.5,-12.499) AF21(7.501,-12.499) AF22(8.499,-12.499) AF23(9.5,-12.499) AF24(10.5,-12.499) AF25(11.501,-12.499) B1(-12.499,11.501) B2(-11.501,11.501) B3(-10.5,11.501) B4(-9.5,11.501) B5(-8.499,11.501) B6(-7.501,11.501) B7(-6.5,11.501) B8(-5.499,11.501) B9(-4.501,11.501) B10(-3.5,11.501) B11(-2.499,11.501) B12(-1.501,11.501) B13(-0.5,11.501) B14(0.5,11.501) B15(1.501,11.501) B16(2.499,11.501) B17(3.5,11.501) B18(4.501,11.501) B19(5.499,11.501) B20(6.5,11.501) B21(7.501,11.501) B22(8.499,11.501) B23(9.5,11.501) B24(10.5,11.501) B25(11.501,11.501) B26(12.499,11.501) C1(-12.499,10.5) C2(-11.501,10.5) C3(-10.5,10.5) C4(-9.5,10.5) C5(-8.499,10.5) C6(-7.501,10.5) C7(-6.5,10.5) C8(-5.499,10.5) C9(-4.501,10.5) C10(-3.5,10.5) C11(-2.499,10.5) C12(-1.501,10.5) C13(-0.5,10.5) C14(0.5,10.5) C15(1.501,10.5) C16(2.499,10.5) C17(3.5,10.5) C18(4.501,10.5) C19(5.499,10.5) C20(6.5,10.5) C21(7.501,10.5) C22(8.499,10.5) C23(9.5,10.5) C24(10.5,10.5) C25(11.501,10.5) C26(12.499,10.5) D1(-12.499,9.5) D2(-11.501,9.5) D3(-10.5,9.5) D4(-9.5,9.5) D5(-8.499,9.5) D6(-7.501,9.5) D7(-6.5,9.5) D8(-5.499,9.5) D9(-4.501,9.5) D10(-3.5,9.5) D11(-2.499,9.5) D12(-1.501,9.5) D13(-0.5,9.5) D14(0.5,9.5) D15(1.501,9.5) D16(2.499,9.5) D17(3.5,9.5) D18(4.501,9.5) D19(5.499,9.5) D20(6.5,9.5) D21(7.501,9.5) D22(8.499,9.5) D23(9.5,9.5) D24(10.5,9.5) D25(11.501,9.5) D26(12.499,9.5) E1(-12.499,8.499) E2(-11.501,8.499) E3(-10.5,8.499) E4(-9.5,8.499) E5(-8.499,8.499) E6(-7.501,8.499) E7(-6.5,8.499) E8(-5.499,8.499) E9(-4.501,8.499) E10(-3.5,8.499) E11(-2.499,8.499) E12(-1.501,8.499) E13(-0.5,8.499) E14(0.5,8.499) E15(1.501,8.499) E16(2.499,8.499) E17(3.5,8.499) E18(4.501,8.499) E19(5.499,8.499) E20(6.5,8.499) E21(7.501,8.499) E22(8.499,8.499) E23(9.5,8.499) E24(10.5,8.499) E25(11.501,8.499) E26(12.499,8.499) F1(-12.499,7.501) F2(-11.501,7.501) F3(-10.5,7.501) F4(-9.5,7.501) F5(-8.499,7.501) F6(-7.501,7.501) F7(-6.5,7.501) F8(-5.499,7.501) F9(-4.501,7.501) F10(-3.5,7.501) F11(-2.499,7.501) F12(-1.501,7.501) F13(-0.5,7.501) F14(0.5,7.501) F15(1.501,7.501) F16(2.499,7.501) F17(3.5,7.501) F18(4.501,7.501) F19(5.499,7.501) F20(6.5,7.501) F21(7.501,7.501) F22(8.499,7.501) F23(9.5,7.501) F24(10.5,7.501) F25(11.501,7.501) F26(12.499,7.501) G1(-12.499,6.5) G2(-11.501,6.5) G3(-10.5,6.5) G4(-9.5,6.5) G5(-8.499,6.5) G6(-7.501,6.5) G7(-6.5,6.5) G8(-5.499,6.5) G9(-4.501,6.5) G10(-3.5,6.5) G11(-2.499,6.5) G12(-1.501,6.5) G13(-0.5,6.5) G14(0.5,6.5) G15(1.501,6.5) G16(2.499,6.5) G17(3.5,6.5) G18(4.501,6.5) G19(5.499,6.5) G20(6.5,6.5) G21(7.501,6.5) G22(8.499,6.5) G23(9.5,6.5) G24(10.5,6.5) G25(11.501,6.5) G26(12.499,6.5) H1(-12.499,5.499) H2(-11.501,5.499) H3(-10.5,5.499) H4(-9.5,5.499) H5(-8.499,5.499) H6(-7.501,5.499) H7(-6.5,5.499) H8(-5.499,5.499) H9(-4.501,5.499) H10(-3.5,5.499) H11(-2.499,5.499) H12(-1.501,5.499) H13(-0.5,5.499) H14(0.5,5.499) H15(1.501,5.499) H16(2.499,5.499) H17(3.5,5.499) H18(4.501,5.499) H19(5.499,5.499) H20(6.5,5.499) H21(7.501,5.499) H22(8.499,5.499) H23(9.5,5.499) H24(10.5,5.499) H25(11.501,5.499) H26(12.499,5.499) J1(-12.499,4.501) J2(-11.501,4.501) J3(-10.5,4.501) J4(-9.5,4.501) J5(-8.499,4.501) J6(-7.501,4.501) J7(-6.5,4.501) J8(-5.499,4.501) J10(-3.5,4.501) J11(-2.499,4.501) J12(-1.501,4.501) J13(-0.5,4.501) J14(0.5,4.501) J15(1.501,4.501) J16(2.499,4.501) J17(3.5,4.501) J19(5.499,4.501) J20(6.5,4.501) J21(7.501,4.501) J22(8.499,4.501) J23(9.5,4.501) J24(10.5,4.501) J25(11.501,4.501) J26(12.499,4.501) K1(-12.499,3.5) K2(-11.501,3.5) K3(-10.5,3.5) K4(-9.5,3.5) K5(-8.499,3.5) K6(-7.501,3.5) K7(-6.5,3.5) K8(-5.499,3.5) K9(-4.501,3.5) K10(-3.5,3.5) K11(-2.499,3.5) K12(-1.501,3.5) K13(-0.5,3.5) K14(0.5,3.5) K15(1.501,3.5) K16(2.499,3.5) K17(3.5,3.5) K18(4.501,3.5) K19(5.499,3.5) K20(6.5,3.5) K21(7.501,3.5) K22(8.499,3.5) K23(9.5,3.5) K24(10.5,3.5) K25(11.501,3.5) K26(12.499,3.5) L1(-12.499,2.499) L2(-11.501,2.499) L3(-10.5,2.499) L4(-9.5,2.499) L5(-8.499,2.499) L6(-7.501,2.499) L7(-6.5,2.499) L8(-5.499,2.499) L9(-4.501,2.499) L10(-3.5,2.499) L11(-2.499,2.499) L12(-1.501,2.499) L13(-0.5,2.499) L14(0.5,2.499) L15(1.501,2.499) L16(2.499,2.499) L17(3.5,2.499) L18(4.501,2.499) L19(5.499,2.499) L20(6.5,2.499) L21(7.501,2.499) L22(8.499,2.499) L23(9.5,2.499) L24(10.5,2.499) L25(11.501,2.499) L26(12.499,2.499) M1(-12.499,1.501) M2(-11.501,1.501) M3(-10.5,1.501) M4(-9.5,1.501) M5(-8.499,1.501) M6(-7.501,1.501) M7(-6.5,1.501) M8(-5.499,1.501) M9(-4.501,1.501) M10(-3.5,1.501) M11(-2.499,1.501) M12(-1.501,1.501) M13(-0.5,1.501) M14(0.5,1.501) M15(1.501,1.501) M16(2.499,1.501) M17(3.5,1.501) M18(4.501,1.501) M19(5.499,1.501) M20(6.5,1.501) M21(7.501,1.501) M22(8.499,1.501) M23(9.5,1.501) M24(10.5,1.501) M25(11.501,1.501) M26(12.499,1.501) N1(-12.499,0.5) N2(-11.501,0.5) N3(-10.5,0.5) N4(-9.5,0.5) N5(-8.499,0.5) N6(-7.501,0.5) N7(-6.5,0.5) N8(-5.499,0.5) N9(-4.501,0.5) N10(-3.5,0.5) N11(-2.499,0.5) N12(-1.501,0.5) N13(-0.5,0.5) N14(0.5,0.5) N15(1.501,0.5) N16(2.499,0.5) N17(3.5,0.5) N18(4.501,0.5) N19(5.499,0.5) N20(6.5,0.5) N21(7.501,0.5) N22(8.499,0.5) N23(9.5,0.5) N24(10.5,0.5) N25(11.501,0.5) N26(12.499,0.5) P1(-12.499,-0.5) P2(-11.501,-0.5) P3(-10.5,-0.5) P4(-9.5,-0.5) P5(-8.499,-0.5) P6(-7.501,-0.5) P7(-6.5,-0.5) P8(-5.499,-0.5) P9(-4.501,-0.5) P10(-3.5,-0.5) P11(-2.499,-0.5) P12(-1.501,-0.5) P13(-0.5,-0.5) P14(0.5,-0.5) P15(1.501,-0.5) P16(2.499,-0.5) P17(3.5,-0.5) P18(4.501,-0.5) P19(5.499,-0.5) P20(6.5,-0.5) P21(7.501,-0.5) P22(8.499,-0.5) P23(9.5,-0.5) P24(10.5,-0.5) P25(11.501,-0.5) P26(12.499,-0.5) R1(-12.499,-1.501) R2(-11.501,-1.501) R3(-10.5,-1.501) R4(-9.5,-1.501) R5(-8.499,-1.501) R6(-7.501,-1.501) R7(-6.5,-1.501) R8(-5.499,-1.501) R9(-4.501,-1.501) R10(-3.5,-1.501) R11(-2.499,-1.501) R12(-1.501,-1.501) R13(-0.5,-1.501) R14(0.5,-1.501) R15(1.501,-1.501) R16(2.499,-1.501) R17(3.5,-1.501) R18(4.501,-1.501) R19(5.499,-1.501) R20(6.5,-1.501) R21(7.501,-1.501) R22(8.499,-1.501) R23(9.5,-1.501) R24(10.5,-1.501) R25(11.501,-1.501) R26(12.499,-1.501) T1(-12.499,-2.499) T2(-11.501,-2.499) T3(-10.5,-2.499) T4(-9.5,-2.499) T5(-8.499,-2.499) T6(-7.501,-2.499) T7(-6.5,-2.499) T8(-5.499,-2.499) T9(-4.501,-2.499) T10(-3.5,-2.499) T11(-2.499,-2.499) T12(-1.501,-2.499) T13(-0.5,-2.499) T14(0.5,-2.499) T15(1.501,-2.499) T16(2.499,-2.499) T17(3.5,-2.499) T18(4.501,-2.499) T19(5.499,-2.499) T20(6.5,-2.499) T21(7.501,-2.499) T22(8.499,-2.499) T23(9.5,-2.499) T24(10.5,-2.499) T25(11.501,-2.499) T26(12.499,-2.499) U1(-12.499,-3.5) U2(-11.501,-3.5) U3(-10.5,-3.5) U4(-9.5,-3.5) U5(-8.499,-3.5) U6(-7.501,-3.5) U7(-6.5,-3.5) U8(-5.499,-3.5) U9(-4.501,-3.5) U10(-3.5,-3.5) U11(-2.499,-3.5) U12(-1.501,-3.5) U13(-0.5,-3.5) U14(0.5,-3.5) U15(1.501,-3.5) U16(2.499,-3.5) U17(3.5,-3.5) U18(4.501,-3.5) U19(5.499,-3.5) U20(6.5,-3.5) U21(7.501,-3.5) U22(8.499,-3.5) U23(9.5,-3.5) U24(10.5,-3.5) U25(11.501,-3.5) U26(12.499,-3.5) V1(-12.499,-4.501) V2(-11.501,-4.501) V3(-10.5,-4.501) V4(-9.5,-4.501) V5(-8.499,-4.501) V6(-7.501,-4.501) V7(-6.5,-4.501) V8(-5.499,-4.501) V10(-3.5,-4.501) V11(-2.499,-4.501) V12(-1.501,-4.501) V13(-0.5,-4.501) V14(0.5,-4.501) V15(1.501,-4.501) V16(2.499,-4.501) V17(3.5,-4.501) V19(5.499,-4.501) V20(6.5,-4.501) V21(7.501,-4.501) V22(8.499,-4.501) V23(9.5,-4.501) V24(10.5,-4.501) V25(11.501,-4.501) V26(12.499,-4.501) W1(-12.499,-5.499) W2(-11.501,-5.499) W3(-10.5,-5.499) W4(-9.5,-5.499) W5(-8.499,-5.499) W6(-7.501,-5.499) W7(-6.5,-5.499) W8(-5.499,-5.499) W9(-4.501,-5.499) W10(-3.5,-5.499) W11(-2.499,-5.499) W12(-1.501,-5.499) W13(-0.5,-5.499) W14(0.5,-5.499) W15(1.501,-5.499) W16(2.499,-5.499) W17(3.5,-5.499) W18(4.501,-5.499) W19(5.499,-5.499) W20(6.5,-5.499) W21(7.501,-5.499) W22(8.499,-5.499) W23(9.5,-5.499) W24(10.5,-5.499) W25(11.501,-5.499) W26(12.499,-5.499) Y1(-12.499,-6.5) Y2(-11.501,-6.5) Y3(-10.5,-6.5) Y4(-9.5,-6.5) Y5(-8.499,-6.5) Y6(-7.501,-6.5) Y7(-6.5,-6.5) Y8(-5.499,-6.5) Y9(-4.501,-6.5) Y10(-3.5,-6.5) Y11(-2.499,-6.5) Y12(-1.501,-6.5) Y13(-0.5,-6.5) Y14(0.5,-6.5) Y15(1.501,-6.5) Y16(2.499,-6.5) Y17(3.5,-6.5) Y18(4.501,-6.5) Y19(5.499,-6.5) Y20(6.5,-6.5) Y21(7.501,-6.5) Y22(8.499,-6.5) Y23(9.5,-6.5) Y24(10.5,-6.5) Y25(11.501,-6.5) Y26(12.499,-6.5)
BLKCON_2X1
  rect 1.524x1.524 hole 0.914: 1(0,1.27)
  round 1.524 hole 0.914: 2(0,-1.27)
BLKCON_3X1
  rect 1.524x1.524 hole 0.914: 1(0,0)
  round 1.524 hole 0.914: 2(2.54,0) 3(5.08,0)
BLKCON_3X2
  rect 1.524x1.524 hole 0.914: 1(0,2.54)
  round 1.524 hole 0.914: 2(2.54,2.54) 3(0,0) 4(2.54,0) 5(0,-2.54) 6(2.54,-2.54)
BLKCON_5X2
  rect 1.473x1.473 hole 0.94: 1(-1.27,5.08)
  round 1.473 hole 0.94: 2(1.27,5.08) 3(-1.27,2.54) 4(1.27,2.54) 5(-1.27,0) 6(1.27,0) 7(-1.27,-2.54) 8(1.27,-2.54) 9(-1.27,-5.08) 10(1.27,-5.08)
BLKCON_10X3
  rect 1.524x1.524 hole 0.914: 1(-2.54,11.43)
  round 1.524 hole 0.914: 2(0,11.43) 3(2.54,11.43) 4(-2.54,8.89) 5(0,8.89) 6(2.54,8.89) 7(-2.54,6.35) 8(0,6.35) 9(2.54,6.35) 10(-2.54,3.81) 11(0,3.81) 12(2.54,3.81) 13(-2.54,1.27) 14(0,1.27) 15(2.54,1.27) 16(-2.54,-1.27) 17(0,-1.27) 18(2.54,-1.27) 19(-2.54,-3.81) 20(0,-3.81) 21(2.54,-3.81) 22(-2.54,-6.35) 23(0,-6.35) 24(2.54,-6.35) 25(-2.54,-8.89) 26(0,-8.89) 27(2.54,-8.89) 28(-2.54,-11.43) 29(0,-11.43) 30(2.54,-11.43)
